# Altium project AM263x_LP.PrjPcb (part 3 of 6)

## Sheet PROC111_AM263x_7_PRU.SchDoc
size 431 x 279 mm; Date: Not shown in title block; ApprovedBy: Not shown in title block; CheckedBy: Not shown in title block; Author: Not shown in title block; CompanyName: Not shown in title block; Engineer: Not shown in title block; Organization: Not shown in title block; Address1: Not shown in title block; Address2: Not shown in title block; Address3: Not shown in title block; Address4: Not shown in title block; DocumentNumber: 11; Revision: Use project parameter SCH_Rev; SheetNumber: 11; SheetTotal: 24; PageSetup: Record=PageOptions¦CenterHorizontal=True¦CenterVertical=True¦PrintScale=1.00¦XCorrection=1.00¦YCorrection=1.00¦PrintKind=0¦BorderSize=5000000¦LeftOffset=0¦BottomOffset=0¦Orientation=2¦PaperLength=1000¦PaperWidth=1000¦Scale=100¦PaperSource=15¦PrintQuality=600¦MediaType=1¦DitherType=10¦PaperKind=Letter¦PrintScaleMode=1
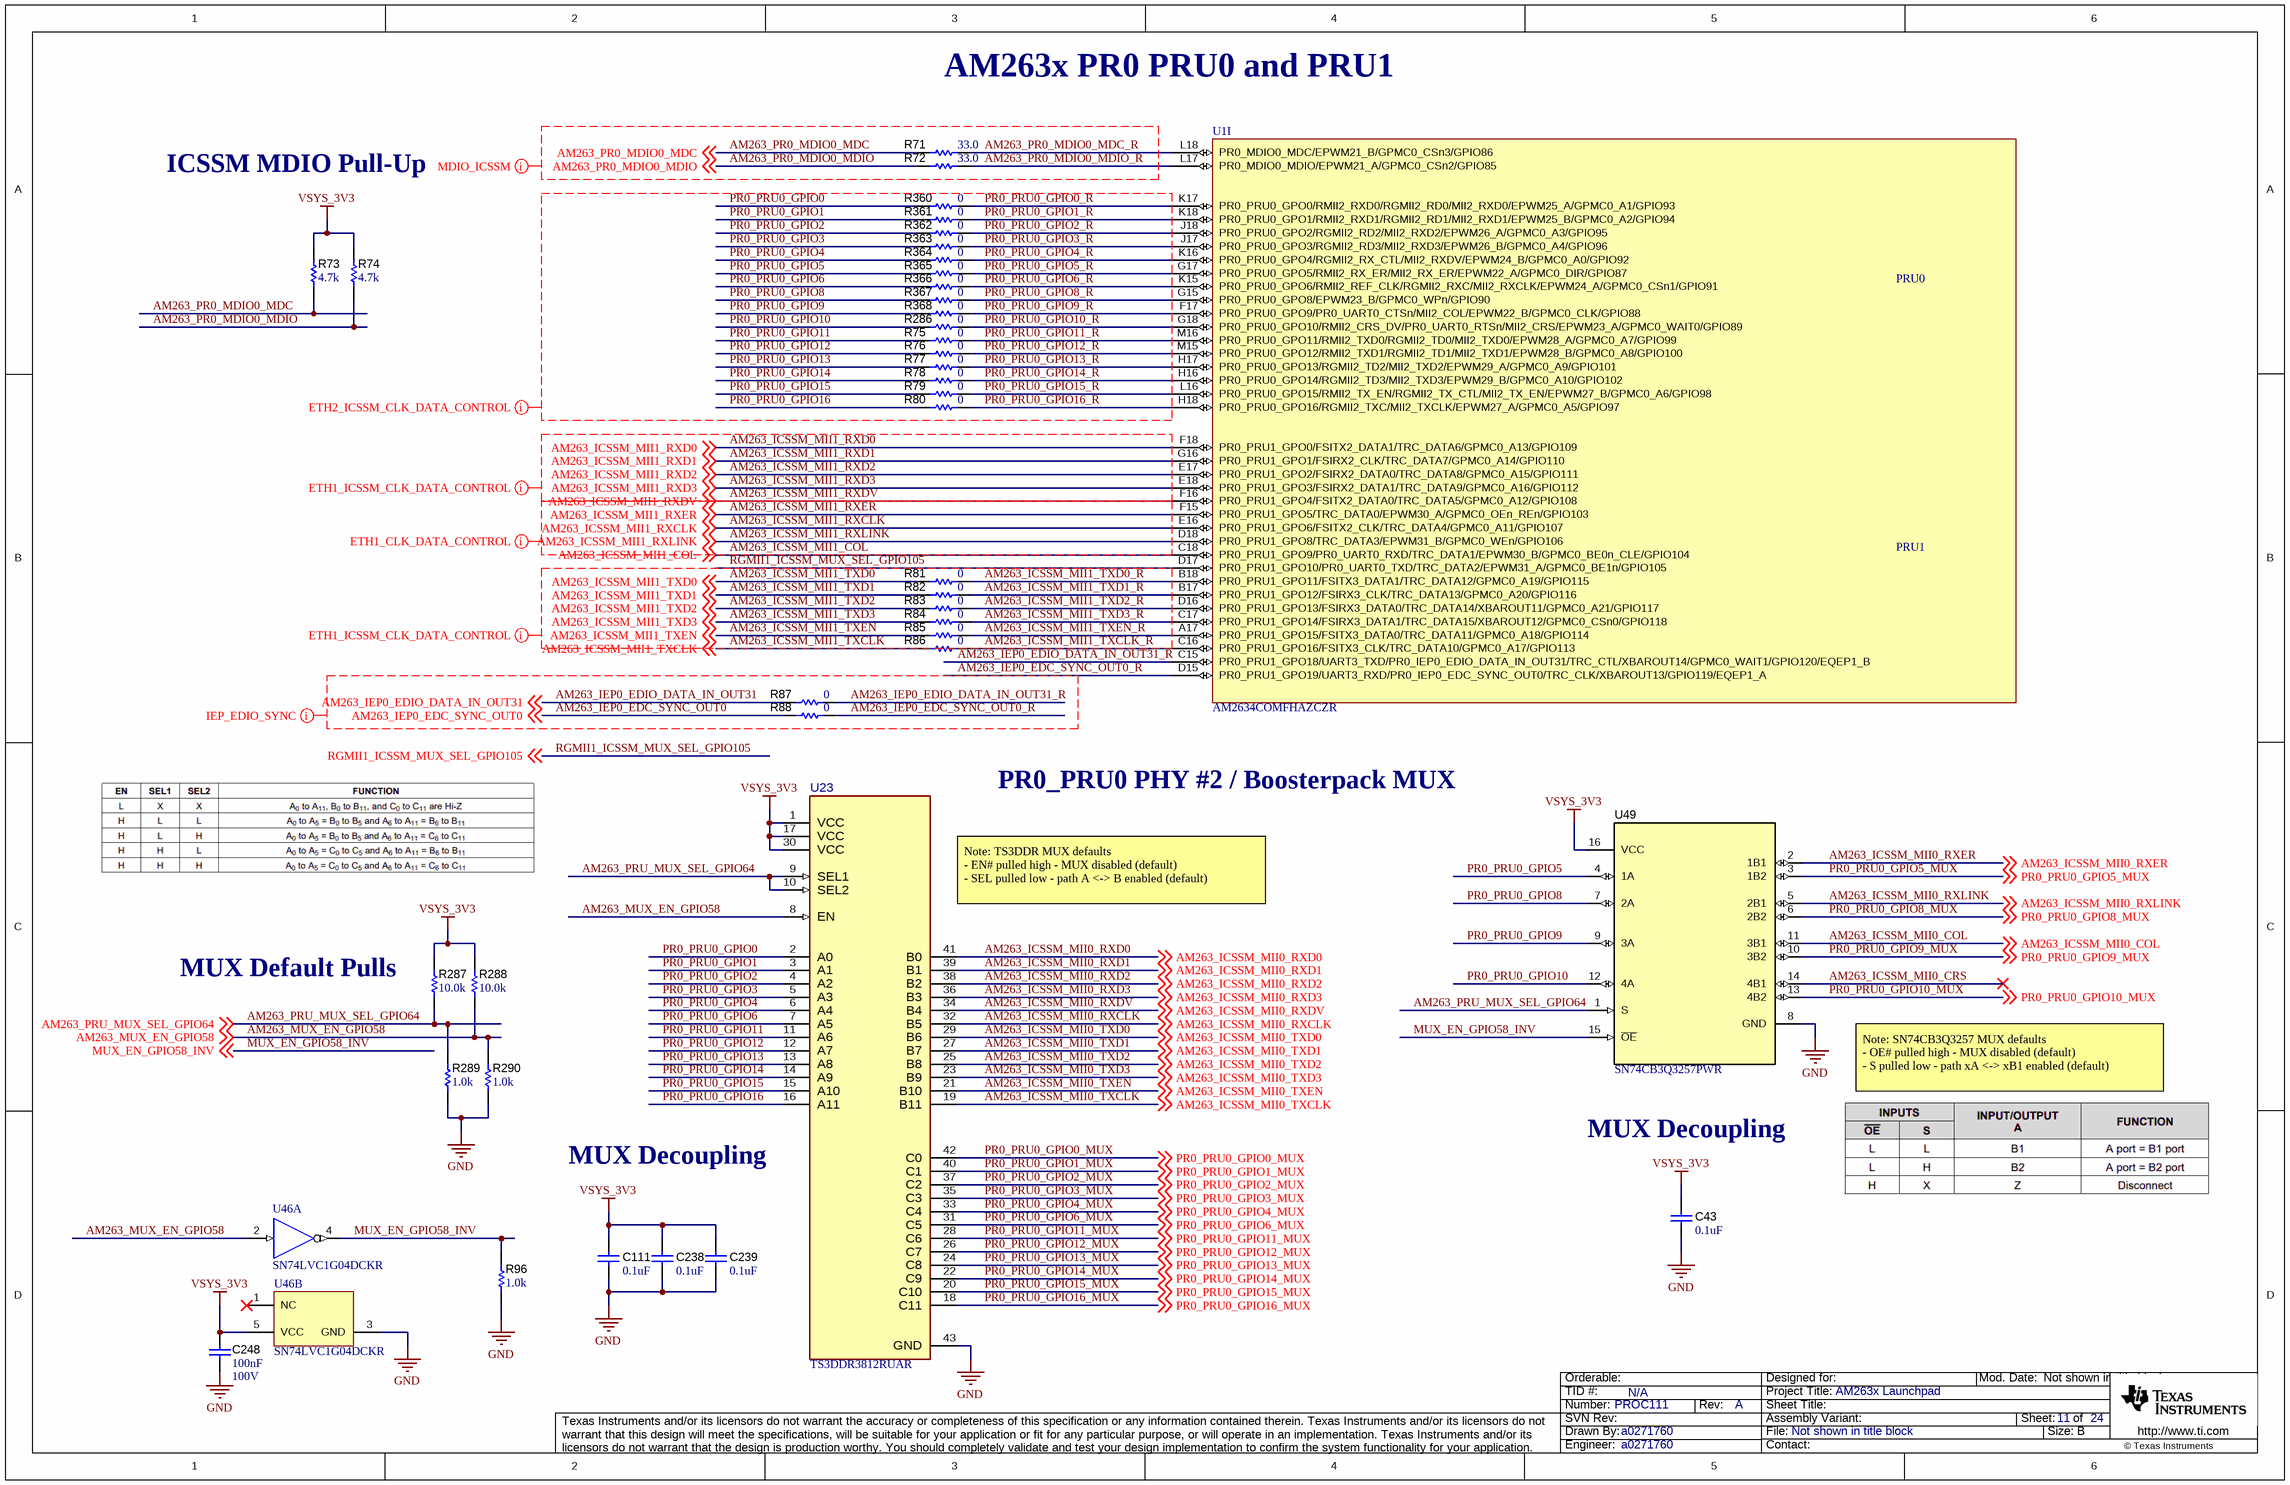
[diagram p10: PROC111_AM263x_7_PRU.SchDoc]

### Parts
C43  ValueDisplayed: 0.1uF  [0402]  (hidden comment: GRM155R71E104KE14D)
C111  ValueDisplayed: 0.1uF  [0402]  (hidden comment: GRM155R71E104KE14D)
C238  ValueDisplayed: 0.1uF  [0402]  (hidden comment: GRM155R71E104KE14D)
C239  ValueDisplayed: 0.1uF  [0402]  (hidden comment: GRM155R71E104KE14D)
C248  Cap_F: 100nF  VDC_V: 100V  [0603]  (hidden comment: GRM188R72A104KA35D)
R71  ValueDisplayed: 33.0  [0402L]  (hidden comment: ERJ-2RKF33R0X)
R72  ValueDisplayed: 33.0  [0402L]  (hidden comment: ERJ-2RKF33R0X)
R73  ValueDisplayed: 4.7k  [0402]  (hidden comment: CRCW04024K70JNED)
R74  ValueDisplayed: 4.7k  [0402]  (hidden comment: CRCW04024K70JNED)
R75  value 0  [0402L]  (hidden comment: ERJ-2GE0R00X)
R76  value 0  [0402L]  (hidden comment: ERJ-2GE0R00X)
R77  value 0  [0402L]  (hidden comment: ERJ-2GE0R00X)
R78  value 0  [0402L]  (hidden comment: ERJ-2GE0R00X)
R79  value 0  [0402L]  (hidden comment: ERJ-2GE0R00X)
R80  value 0  [0402L]  (hidden comment: ERJ-2GE0R00X)
R81  value 0  [0402L]  (hidden comment: ERJ-2GE0R00X)
R82  value 0  [0402L]  (hidden comment: ERJ-2GE0R00X)
R83  value 0  [0402L]  (hidden comment: ERJ-2GE0R00X)
R84  value 0  [0402L]  (hidden comment: ERJ-2GE0R00X)
R85  value 0  [0402L]  (hidden comment: ERJ-2GE0R00X)
R86  value 0  [0402L]  (hidden comment: ERJ-2GE0R00X)
R87  value 0  [0402L]  (hidden comment: ERJ-2GE0R00X)
R88  value 0  [0402L]  (hidden comment: ERJ-2GE0R00X)
R96  ValueDisplayed: 1.0k  [0402]  (hidden comment: ERJ-2GEJ102X)
R286  value 0  [0402L]  (hidden comment: ERJ-2GE0R00X)
R287  ValueDisplayed: 10.0k  [0402]  (hidden comment: ERJ-2RKF1002X)
R288  ValueDisplayed: 10.0k  [0402]  (hidden comment: ERJ-2RKF1002X)
R289  ValueDisplayed: 1.0k  [0402]  (hidden comment: ERJ-2GEJ102X)
R290  ValueDisplayed: 1.0k  [0402]  (hidden comment: ERJ-2GEJ102X)
R360  value 0  [0402L]  (hidden comment: ERJ-2GE0R00X)
R361  value 0  [0402L]  (hidden comment: ERJ-2GE0R00X)
R362  value 0  [0402L]  (hidden comment: ERJ-2GE0R00X)
R363  value 0  [0402L]  (hidden comment: ERJ-2GE0R00X)
R364  value 0  [0402L]  (hidden comment: ERJ-2GE0R00X)
R365  value 0  [0402L]  (hidden comment: ERJ-2GE0R00X)
R366  value 0  [0402L]  (hidden comment: ERJ-2GE0R00X)
R367  value 0  [0402L]  (hidden comment: ERJ-2GE0R00X)
R368  value 0  [0402L]  (hidden comment: ERJ-2GE0R00X)
U1  AM2634COMFHAZCZR  [ZCZ (S-PBGA-N324)]  (part I of 13)
U23  TS3DDR3812RUAR  [RUA0042A-MFG]
U46  SN74LVC1G04DCKR  [DCK0005A_N]  (parts A,B of 2)
U49  SN74CB3Q3257PWR  [PW0016A_L]

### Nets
GND: C43.1 C111.1 C238.1 C239.1 C248.2 R96.1 R289.1 R290.1 U23.43(GND) U46.3(GND) U49.8(GND)
VSYS_3V3: C43.2 C111.2 C238.2 C239.2 C248.1 R73.2 R74.2 R287.1 R288.1 U23.1(VCC) U23.17(VCC) U23.30(VCC) U46.5(VCC) U49.16(VCC)
AM263_ICSSM_MII0_COL: U49.11(3B1) ; off-sheet AM263_ICSSM_MII0_COL
AM263_ICSSM_MII0_CRS: U49.14(4B1)
AM263_ICSSM_MII0_RXCLK: U23.32(B5) ; off-sheet AM263_ICSSM_MII0_RXCLK
AM263_ICSSM_MII0_RXD0: U23.41(B0) ; off-sheet AM263_ICSSM_MII0_RXD0
AM263_ICSSM_MII0_RXD1: U23.39(B1) ; off-sheet AM263_ICSSM_MII0_RXD1
AM263_ICSSM_MII0_RXD2: U23.38(B2) ; off-sheet AM263_ICSSM_MII0_RXD2
AM263_ICSSM_MII0_RXD3: U23.36(B3) ; off-sheet AM263_ICSSM_MII0_RXD3
AM263_ICSSM_MII0_RXDV: U23.34(B4) ; off-sheet AM263_ICSSM_MII0_RXDV
AM263_ICSSM_MII0_RXER: U49.2(1B1) ; off-sheet AM263_ICSSM_MII0_RXER
AM263_ICSSM_MII0_RXLINK: U49.5(2B1) ; off-sheet AM263_ICSSM_MII0_RXLINK
AM263_ICSSM_MII0_TXCLK: U23.19(B11) ; off-sheet AM263_ICSSM_MII0_TXCLK
AM263_ICSSM_MII0_TXD0: U23.29(B6) ; off-sheet AM263_ICSSM_MII0_TXD0
AM263_ICSSM_MII0_TXD1: U23.27(B7) ; off-sheet AM263_ICSSM_MII0_TXD1
AM263_ICSSM_MII0_TXD2: U23.25(B8) ; off-sheet AM263_ICSSM_MII0_TXD2
AM263_ICSSM_MII0_TXD3: U23.23(B9) ; off-sheet AM263_ICSSM_MII0_TXD3
AM263_ICSSM_MII0_TXEN: U23.21(B10) ; off-sheet AM263_ICSSM_MII0_TXEN
AM263_ICSSM_MII1_COL: U1.C18(PR0_PRU1_GPO9/PR0_UART0_RXD/TRC_DATA1/EPWM30_B/GPMC0_BE0n_CLE/GPIO104) ; off-sheet AM263_ICSSM_MII1_COL
AM263_ICSSM_MII1_RXCLK: U1.E16(PR0_PRU1_GPO6/FSITX2_CLK/TRC_DATA4/GPMC0_A11/GPIO107) ; off-sheet AM263_ICSSM_MII1_RXCLK
AM263_ICSSM_MII1_RXD0: U1.F18(PR0_PRU1_GPO0/FSITX2_DATA1/TRC_DATA6/GPMC0_A13/GPIO109) ; off-sheet AM263_ICSSM_MII1_RXD0
AM263_ICSSM_MII1_RXD1: U1.G16(PR0_PRU1_GPO1/FSIRX2_CLK/TRC_DATA7/GPMC0_A14/GPIO110) ; off-sheet AM263_ICSSM_MII1_RXD1
AM263_ICSSM_MII1_RXD2: U1.E17(PR0_PRU1_GPO2/FSIRX2_DATA0/TRC_DATA8/GPMC0_A15/GPIO111) ; off-sheet AM263_ICSSM_MII1_RXD2
AM263_ICSSM_MII1_RXD3: U1.E18(PR0_PRU1_GPO3/FSIRX2_DATA1/TRC_DATA9/GPMC0_A16/GPIO112) ; off-sheet AM263_ICSSM_MII1_RXD3
AM263_ICSSM_MII1_RXDV: U1.F16(PR0_PRU1_GPO4/FSITX2_DATA0/TRC_DATA5/GPMC0_A12/GPIO108) ; off-sheet AM263_ICSSM_MII1_RXDV
AM263_ICSSM_MII1_RXER: U1.F15(PR0_PRU1_GPO5/TRC_DATA0/EPWM30_A/GPMC0_OEn_REn/GPIO103) ; off-sheet AM263_ICSSM_MII1_RXER
AM263_ICSSM_MII1_RXLINK: U1.D18(PR0_PRU1_GPO8/TRC_DATA3/EPWM31_B/GPMC0_WEn/GPIO106) ; off-sheet AM263_ICSSM_MII1_RXLINK
AM263_ICSSM_MII1_TXCLK: R86.1 ; off-sheet AM263_ICSSM_MII1_TXCLK
AM263_ICSSM_MII1_TXCLK_R: R86.2 U1.C16(PR0_PRU1_GPO16/FSITX3_CLK/TRC_DATA10/GPMC0_A17/GPIO113)
AM263_ICSSM_MII1_TXD0: R81.1 ; off-sheet AM263_ICSSM_MII1_TXD0
AM263_ICSSM_MII1_TXD0_R: R81.2 U1.B18(PR0_PRU1_GPO11/FSITX3_DATA1/TRC_DATA12/GPMC0_A19/GPIO115)
AM263_ICSSM_MII1_TXD1: R82.1 ; off-sheet AM263_ICSSM_MII1_TXD1
AM263_ICSSM_MII1_TXD1_R: R82.2 U1.B17(PR0_PRU1_GPO12/FSIRX3_CLK/TRC_DATA13/GPMC0_A20/GPIO116)
AM263_ICSSM_MII1_TXD2: R83.1 ; off-sheet AM263_ICSSM_MII1_TXD2
AM263_ICSSM_MII1_TXD2_R: R83.2 U1.D16(PR0_PRU1_GPO13/FSIRX3_DATA0/TRC_DATA14/XBAROUT11/GPMC0_A21/GPIO117)
AM263_ICSSM_MII1_TXD3: R84.1 ; off-sheet AM263_ICSSM_MII1_TXD3
AM263_ICSSM_MII1_TXD3_R: R84.2 U1.C17(PR0_PRU1_GPO14/FSIRX3_DATA1/TRC_DATA15/XBAROUT12/GPMC0_CSn0/GPIO118)
AM263_ICSSM_MII1_TXEN: R85.1 ; off-sheet AM263_ICSSM_MII1_TXEN
AM263_ICSSM_MII1_TXEN_R: R85.2 U1.A17(PR0_PRU1_GPO15/FSITX3_DATA0/TRC_DATA11/GPMC0_A18/GPIO114)
AM263_IEP0_EDC_SYNC_OUT0: R88.1 ; off-sheet AM263_IEP0_EDC_SYNC_OUT0
AM263_IEP0_EDC_SYNC_OUT0_R: R88.2 U1.D15(PR0_PRU1_GPO19/UART3_RXD/PR0_IEP0_EDC_SYNC_OUT0/TRC_CLK/XBAROUT13/GPIO119/EQEP1_A)
AM263_IEP0_EDIO_DATA_IN_OUT31: R87.1 ; off-sheet AM263_IEP0_EDIO_DATA_IN_OUT31
AM263_IEP0_EDIO_DATA_IN_OUT31_R: R87.2 U1.C15(PR0_PRU1_GPO18/UART3_TXD/PR0_IEP0_EDIO_DATA_IN_OUT31/TRC_CTL/XBAROUT14/GPMC0_WAIT1/GPIO120/EQEP1_B)
AM263_MUX_EN_GPIO58: R288.2 R290.2 U23.8(EN) U46.2(A) ; off-sheet AM263_MUX_EN_GPIO58
AM263_PR0_MDIO0_MDC: R71.1 R73.1 ; off-sheet AM263_PR0_MDIO0_MDC
AM263_PR0_MDIO0_MDC_R: R71.2 U1.L18(PR0_MDIO0_MDC/EPWM21_B/GPMC0_CSn3/GPIO86)
AM263_PR0_MDIO0_MDIO: R72.1 R74.1 ; off-sheet AM263_PR0_MDIO0_MDIO
AM263_PR0_MDIO0_MDIO_R: R72.2 U1.L17(PR0_MDIO0_MDIO/EPWM21_A/GPMC0_CSn2/GPIO85)
AM263_PRU_MUX_SEL_GPIO64: R287.2 R289.2 U23.9(SEL1) U23.10(SEL2) U49.1(S) ; off-sheet AM263_PRU_MUX_SEL_GPIO64
MUX_EN_GPIO58_INV: R96.2 U46.4(Y) U49.15(~{OE}) ; off-sheet MUX_EN_GPIO58_INV
PR0_PRU0_GPIO0: R360.1 U23.2(A0)
PR0_PRU0_GPIO0_MUX: U23.42(C0) ; off-sheet PR0_PRU0_GPIO0_MUX
PR0_PRU0_GPIO0_R: R360.2 U1.K17(PR0_PRU0_GPO0/RMII2_RXD0/RGMII2_RD0/MII2_RXD0/EPWM25_A/GPMC0_A1/GPIO93)
PR0_PRU0_GPIO1: R361.1 U23.3(A1)
PR0_PRU0_GPIO1_MUX: U23.40(C1) ; off-sheet PR0_PRU0_GPIO1_MUX
PR0_PRU0_GPIO1_R: R361.2 U1.K18(PR0_PRU0_GPO1/RMII2_RXD1/RGMII2_RD1/MII2_RXD1/EPWM25_B/GPMC0_A2/GPIO94)
PR0_PRU0_GPIO2: R362.1 U23.4(A2)
PR0_PRU0_GPIO2_MUX: U23.37(C2) ; off-sheet PR0_PRU0_GPIO2_MUX
PR0_PRU0_GPIO2_R: R362.2 U1.J18(PR0_PRU0_GPO2/RGMII2_RD2/MII2_RXD2/EPWM26_A/GPMC0_A3/GPIO95)
PR0_PRU0_GPIO3: R363.1 U23.5(A3)
PR0_PRU0_GPIO3_MUX: U23.35(C3) ; off-sheet PR0_PRU0_GPIO3_MUX
PR0_PRU0_GPIO3_R: R363.2 U1.J17(PR0_PRU0_GPO3/RGMII2_RD3/MII2_RXD3/EPWM26_B/GPMC0_A4/GPIO96)
PR0_PRU0_GPIO4: R364.1 U23.6(A4)
PR0_PRU0_GPIO4_MUX: U23.33(C4) ; off-sheet PR0_PRU0_GPIO4_MUX
PR0_PRU0_GPIO4_R: R364.2 U1.K16(PR0_PRU0_GPO4/RGMII2_RX_CTL/MII2_RXDV/EPWM24_B/GPMC0_A0/GPIO92)
PR0_PRU0_GPIO5: R365.1 U49.4(1A)
PR0_PRU0_GPIO5_MUX: U49.3(1B2) ; off-sheet PR0_PRU0_GPIO5_MUX
PR0_PRU0_GPIO5_R: R365.2 U1.G17(PR0_PRU0_GPO5/RMII2_RX_ER/MII2_RX_ER/EPWM22_A/GPMC0_DIR/GPIO87)
PR0_PRU0_GPIO6: R366.1 U23.7(A5)
PR0_PRU0_GPIO6_MUX: U23.31(C5) ; off-sheet PR0_PRU0_GPIO6_MUX
PR0_PRU0_GPIO6_R: R366.2 U1.K15(PR0_PRU0_GPO6/RMII2_REF_CLK/RGMII2_RXC/MII2_RXCLK/EPWM24_A/GPMC0_CSn1/GPIO91)
PR0_PRU0_GPIO8: R367.1 U49.7(2A)
PR0_PRU0_GPIO8_MUX: U49.6(2B2) ; off-sheet PR0_PRU0_GPIO8_MUX
PR0_PRU0_GPIO8_R: R367.2 U1.G15(PR0_PRU0_GPO8/EPWM23_B/GPMC0_WPn/GPIO90)
PR0_PRU0_GPIO9: R368.1 U49.9(3A)
PR0_PRU0_GPIO9_MUX: U49.10(3B2) ; off-sheet PR0_PRU0_GPIO9_MUX
PR0_PRU0_GPIO9_R: R368.2 U1.F17(PR0_PRU0_GPO9/PR0_UART0_CTSn/MII2_COL/EPWM22_B/GPMC0_CLK/GPIO88)
PR0_PRU0_GPIO10: R286.1 U49.12(4A)
PR0_PRU0_GPIO10_MUX: U49.13(4B2) ; off-sheet PR0_PRU0_GPIO10_MUX
PR0_PRU0_GPIO10_R: R286.2 U1.G18(PR0_PRU0_GPO10/RMII2_CRS_DV/PR0_UART0_RTSn/MII2_CRS/EPWM23_A/GPMC0_WAIT0/GPIO89)
PR0_PRU0_GPIO11: R75.1 U23.11(A6)
PR0_PRU0_GPIO11_MUX: U23.28(C6) ; off-sheet PR0_PRU0_GPIO11_MUX
PR0_PRU0_GPIO11_R: R75.2 U1.M16(PR0_PRU0_GPO11/RMII2_TXD0/RGMII2_TD0/MII2_TXD0/EPWM28_A/GPMC0_A7/GPIO99)
PR0_PRU0_GPIO12: R76.1 U23.12(A7)
PR0_PRU0_GPIO12_MUX: U23.26(C7) ; off-sheet PR0_PRU0_GPIO12_MUX
PR0_PRU0_GPIO12_R: R76.2 U1.M15(PR0_PRU0_GPO12/RMII2_TXD1/RGMII2_TD1/MII2_TXD1/EPWM28_B/GPMC0_A8/GPIO100)
PR0_PRU0_GPIO13: R77.1 U23.13(A8)
PR0_PRU0_GPIO13_MUX: U23.24(C8) ; off-sheet PR0_PRU0_GPIO13_MUX
PR0_PRU0_GPIO13_R: R77.2 U1.H17(PR0_PRU0_GPO13/RGMII2_TD2/MII2_TXD2/EPWM29_A/GPMC0_A9/GPIO101)
PR0_PRU0_GPIO14: R78.1 U23.14(A9)
PR0_PRU0_GPIO14_MUX: U23.22(C9) ; off-sheet PR0_PRU0_GPIO14_MUX
PR0_PRU0_GPIO14_R: R78.2 U1.H16(PR0_PRU0_GPO14/RGMII2_TD3/MII2_TXD3/EPWM29_B/GPMC0_A10/GPIO102)
PR0_PRU0_GPIO15: R79.1 U23.15(A10)
PR0_PRU0_GPIO15_MUX: U23.20(C10) ; off-sheet PR0_PRU0_GPIO15_MUX
PR0_PRU0_GPIO15_R: R79.2 U1.L16(PR0_PRU0_GPO15/RMII2_TX_EN/RGMII2_TX_CTL/MII2_TX_EN/EPWM27_B/GPMC0_A6/GPIO98)
PR0_PRU0_GPIO16: R80.1 U23.16(A11)
PR0_PRU0_GPIO16_MUX: U23.18(C11) ; off-sheet PR0_PRU0_GPIO16_MUX
PR0_PRU0_GPIO16_R: R80.2 U1.H18(PR0_PRU0_GPO16/RGMII2_TXC/MII2_TXCLK/EPWM27_A/GPMC0_A5/GPIO97)
RGMII1_ICSSM_MUX_SEL_GPIO105: U1.D17(PR0_PRU1_GPO10/PR0_UART0_TXD/TRC_DATA2/EPWM31_A/GPMC0_BE1n/GPIO105) ; off-sheet RGMII1_ICSSM_MUX_SEL_GPIO105

Not connected (* = marked no-connect by the designer): U46 1(NC)*

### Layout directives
mark named IEP_EDIO_SYNC: AM263_IEP0_EDC_SYNC_OUT0, AM263_IEP0_EDC_SYNC_OUT0_R, AM263_IEP0_EDIO_DATA_IN_OUT31, AM263_IEP0_EDIO_DATA_IN_OUT31_R
mark named ETH2_ICSSM_CLK_DATA_CONTROL: PR0_PRU0_GPIO0, PR0_PRU0_GPIO0_R, PR0_PRU0_GPIO1, PR0_PRU0_GPIO1_R, PR0_PRU0_GPIO2, PR0_PRU0_GPIO2_R, PR0_PRU0_GPIO3, PR0_PRU0_GPIO3_R, PR0_PRU0_GPIO4, PR0_PRU0_GPIO4_R, PR0_PRU0_GPIO5, PR0_PRU0_GPIO5_R, PR0_PRU0_GPIO6, PR0_PRU0_GPIO6_R, PR0_PRU0_GPIO8, PR0_PRU0_GPIO8_R, PR0_PRU0_GPIO9, PR0_PRU0_GPIO9_R, PR0_PRU0_GPIO10, PR0_PRU0_GPIO10_R, PR0_PRU0_GPIO11, PR0_PRU0_GPIO11_R, PR0_PRU0_GPIO12, PR0_PRU0_GPIO12_R, PR0_PRU0_GPIO13, PR0_PRU0_GPIO13_R, PR0_PRU0_GPIO14, PR0_PRU0_GPIO14_R, PR0_PRU0_GPIO15, PR0_PRU0_GPIO15_R, PR0_PRU0_GPIO16, PR0_PRU0_GPIO16_R
mark named ETH1_ICSSM_CLK_DATA_CONTROL: AM263_ICSSM_MII1_RXD0, AM263_ICSSM_MII1_RXD1, AM263_ICSSM_MII1_RXD2, AM263_ICSSM_MII1_RXD3, AM263_ICSSM_MII1_RXDV, AM263_ICSSM_MII1_TXCLK, AM263_ICSSM_MII1_TXCLK_R, AM263_ICSSM_MII1_TXD0, AM263_ICSSM_MII1_TXD0_R, AM263_ICSSM_MII1_TXD1, AM263_ICSSM_MII1_TXD1_R, AM263_ICSSM_MII1_TXD2, AM263_ICSSM_MII1_TXD2_R, AM263_ICSSM_MII1_TXD3, AM263_ICSSM_MII1_TXD3_R, AM263_ICSSM_MII1_TXEN, AM263_ICSSM_MII1_TXEN_R, RGMII1_ICSSM_MUX_SEL_GPIO105
mark named MDIO_ICSSM: AM263_PR0_MDIO0_MDC, AM263_PR0_MDIO0_MDC_R, AM263_PR0_MDIO0_MDIO, AM263_PR0_MDIO0_MDIO_R
mark named ETH1_CLK_DATA_CONTROL: AM263_ICSSM_MII1_COL, AM263_ICSSM_MII1_RXCLK, AM263_ICSSM_MII1_RXDV, AM263_ICSSM_MII1_RXER, AM263_ICSSM_MII1_RXLINK

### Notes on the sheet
- AM263x PR0 PRU0 and PRU1
- ICSSM MDIO Pull-Up
- PR0_PRU0 PHY #2 / Boosterpack MUX
- (near U23) Note: TS3DDR MUX defaults
  - EN# pulled high - MUX disabled (default)
  - SEL pulled low - path A <-> B enabled (default)
- (near R287) MUX Default Pulls
- Note: SN74CB3Q3257 MUX defaults
  - OE# pulled high - MUX disabled (default)
  - S pulled low - path xA <-> xB1 enabled (default)
- MUX Decoupling

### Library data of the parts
C43 C111 C238 C239 = CMP-0006659-2: CAP, CERM, 0.1 uF, 25 V, +/- 10%, X7R, 0402; Manufacturer: MuRata; TaMin_C: -55°C; Polarized: N; SizeAreaWB_mm2: 3; U/M: EA; Value: 0.1uF; TaMax_C: 125°C; SizeZ_mm: 0.6; SizeX_mm: 1; SizeY_mm: 0.5; Value2: 25V; Cap_F: 100nF; AEC Category: Q200; Value1: Unknown
C248 = CMP-0007469-4: CAP, CERM, 0.1 uF, 100 V, +/- 10%, X7R, 0603; Manufacturer: MuRata; TaMin_C: -55°C; Polarized: N; SizeAreaWB_mm2: 4.68; Value1: Unknown; U/M: EA; Value: 0.1uF; TaMax_C: 125°C; SizeZ_mm: 1; SizeX_mm: 1.6; SizeY_mm: 0.8; SizeArea_mm2: 1.28; AEC Category: Q200
R71 R72 = CMP-0026696-1: RES, 33.0, 1%, 0.1 W, 0402; Manufacturer: Panasonic; Power_W: 100mW; TempCo: 100 ppm/C; Value_Code: 33R0; U/M: EA; Value: 33.0; Res_ohm: 33; SizeX_mm: 1; SizeY_mm: 0.5; SizeZ_mm: 0.6; Value2: 0.1W; VDC_V: 50V; AEC Category: Q200
R73 R74 = CMP-0026938-5: RES, 4.7 k, 5%, 0.063 W, AEC-Q200 Grade 0, 0402; Manufacturer: Vishay-Dale; Power_W: 63mW; TempCo: 200 ppm/C; Value_Code: 4k70; Value: 4.7k; EIA_Code: E24; SizeX_mm: 1; SizeY_mm: 0.5; SizeZ_mm: 0.6; Value2: 0.063W; AEC Qualified: Y; VDC_V: 50V; AEC Category: Q200; AEC Grade: 0
R75-R88 R286 R360-R368 = CMP-0026992-3: RES, 0, 5%, 0.1 W, AEC-Q200 Grade 0, 0402; Manufacturer: Panasonic; Power_W: 100mW; TempCo: 600 ppm/C; Value_Code: 0000; EIA_Code: E24; SizeX_mm: 1; SizeY_mm: 0.5; SizeZ_mm: 0.6; Value2: 0.1W; AEC Qualified: Y; VDC_V: 50V; AEC Category: Q200; SizeAreaWB_mm2: 3
R96 R289 R290 = CMP-0078193-1: RES, 1.0 k, 5%, 0.1 W, AEC-Q200 Grade 0, 0402; Manufacturer: Panasonic; Value_Code: 1k00; SizeArea_mm2: 0.5; AEC Qualified: Y; AEC Category: Q200; Res_ohm: 1k; Value: 1.0k; SizeZ_mm: 0.6; Green_REACh: Passed; EIA_Code: E24; TempCo: 200 ppm/C; AEC Grade: 0; Power_W: 100mW; VDC_V: 50V; Value2: 0.1W; Green_Lifecycle: Active; U/M: EA; SizeX_mm: 1
R287 R288 = CMP-0026658-1: RES, 10.0 k, 1%, 0.1 W, 0402; Manufacturer: Panasonic; Power_W: 100mW; TempCo: 100 ppm/C; Value_Code: 10k0; U/M: EA; Value: 10.0k; EIA_Code: E96; Res_ohm: 10k; SizeX_mm: 1; SizeY_mm: 0.5; SizeZ_mm: 0.6; Value2: 0.1W; VDC_V: 50V; AEC Category: Q200
U1 = AM263x: Sitara AM263x MCU; Manufacturer: Texas Instruments
U23 = CMP-0093539-2: IC MUX/DEMUX DDR3 1:2 42WQFN; Manufacturer: Texas Instruments; TaMax_C: +85°C; TaMin_C: -40°C; On State Resistance: 8Ω; SizeZ_mm: 0.8mm; Min Supply Voltage: 3V; Standoff Height: 0mm; Max Supply Voltage: 3.6V; AEC Qualified: No; PositionCount: 12; -3Db Bandwith: 1.675GHz; Nominal Supply Current: 300uA; AEC Category: Q200
U46 = CMP-0051684-3: Single Inverter, DCK0005A, LARGE T&R; Manufacturer: Texas Instruments; Input Type: CMOS/TTL; Output Drive (IOL/IOH)(Max)(mA): 32/-32; Sub-Family: Inverting Buffer/Driver; VCC(Min)(V): 1.65; Bits(#): 1; Schmitt Trigger: No; Technology Family: LVC; Rating: Catalog; ICC @ Nom Voltage(Max)(mA): 0.01; tpd @ Nom Voltage(Max)(ns): 7.5,5.2,4.2,3.7; Voltage(Nom)(V): 1.8,2.5,3.3,5; F @ Nom Voltage(Max)(Mhz): 150; Output Type: CMOS; VCC(Max)(V): 5.5; Logic: Inverting; AEC Category: Q200; AEC Qualified: N; CompType: IC; SizeAreaWB_mm2: 9.3; SizeArea_mm2: 4.2; SizeX_mm: 2.1; SizeY_mm: 2.0; SizeZ_mm: 1.1
U49 = CMP-0076540-1: 4-Bit One-of-2 FET Multiplexer/Demultiplexer 2.5-V/3.3-V Low-Voltage, High-Bandwidth Bus Switch, PW0016A (TSSOP-16); Manufacturer: Texas Instruments; SizeAreaWB_mm2: 58.8; SizeArea_mm2: 32.0; SizeZ_mm: 1.2; SizeY_mm: 5.0; U/M: EA; CompType: IC; SizeX_mm: 6.4

## Sheet PROC111_AM263x_8_SDFM.SchDoc
size 431 x 279 mm; Date: Not shown in title block; ApprovedBy: Not shown in title block; CheckedBy: Not shown in title block; Author: Not shown in title block; CompanyName: Not shown in title block; Engineer: Not shown in title block; Organization: Not shown in title block; Address1: Not shown in title block; Address2: Not shown in title block; Address3: Not shown in title block; Address4: Not shown in title block; DocumentNumber: 12; Revision: Use project parameter SCH_Rev; SheetNumber: 12; SheetTotal: 24; PageSetup: Record=PageOptions¦CenterHorizontal=True¦CenterVertical=True¦PrintScale=1.00¦XCorrection=1.00¦YCorrection=1.00¦PrintKind=0¦BorderSize=5000000¦LeftOffset=0¦BottomOffset=0¦Orientation=2¦PaperLength=1000¦PaperWidth=1000¦Scale=100¦PaperSource=15¦PrintQuality=600¦MediaType=1¦DitherType=10¦PaperKind=Letter¦PrintScaleMode=1
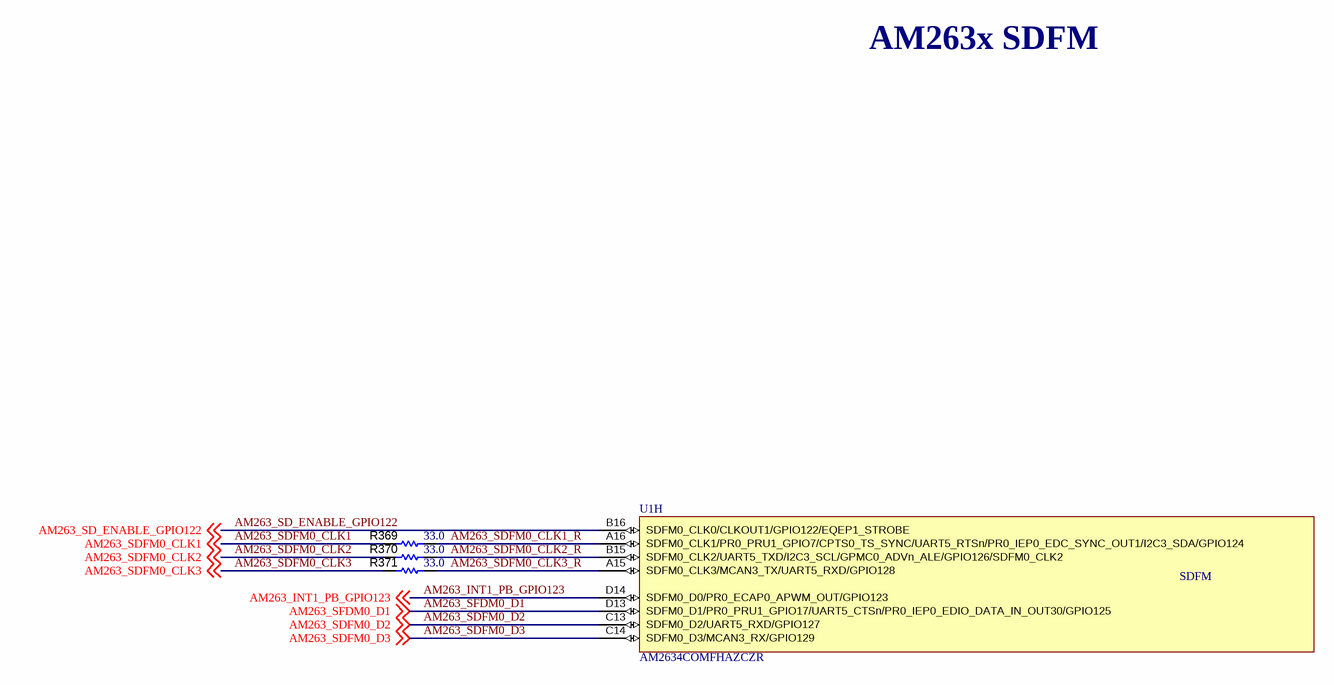
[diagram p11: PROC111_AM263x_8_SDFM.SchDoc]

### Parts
R369  ValueDisplayed: 33.0  [0402L]  (hidden comment: ERJ-2RKF33R0X)
R370  ValueDisplayed: 33.0  [0402L]  (hidden comment: ERJ-2RKF33R0X)
R371  ValueDisplayed: 33.0  [0402L]  (hidden comment: ERJ-2RKF33R0X)
U1  AM2634COMFHAZCZR  [ZCZ (S-PBGA-N324)]  (part H of 13)

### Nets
AM263_INT1_PB_GPIO123: U1.D14(SDFM0_D0/PR0_ECAP0_APWM_OUT/GPIO123) ; off-sheet AM263_INT1_PB_GPIO123
AM263_SD_ENABLE_GPIO122: U1.B16(SDFM0_CLK0/CLKOUT1/GPIO122/EQEP1_STROBE) ; off-sheet AM263_SD_ENABLE_GPIO122
AM263_SDFM0_CLK1: R369.1 ; off-sheet AM263_SDFM0_CLK1
AM263_SDFM0_CLK1_R: R369.2 U1.A16(SDFM0_CLK1/PR0_PRU1_GPIO7/CPTS0_TS_SYNC/UART5_RTSn/PR0_IEP0_EDC_SYNC_OUT1/I2C3_SDA/GPIO124)
AM263_SDFM0_CLK2: R370.1 ; off-sheet AM263_SDFM0_CLK2
AM263_SDFM0_CLK2_R: R370.2 U1.B15(SDFM0_CLK2/UART5_TXD/I2C3_SCL/GPMC0_ADVn_ALE/GPIO126/SDFM0_CLK2)
AM263_SDFM0_CLK3: R371.1 ; off-sheet AM263_SDFM0_CLK3
AM263_SDFM0_CLK3_R: R371.2 U1.A15(SDFM0_CLK3/MCAN3_TX/UART5_RXD/GPIO128)
AM263_SDFM0_D2: U1.C13(SDFM0_D2/UART5_RXD/GPIO127) ; off-sheet AM263_SDFM0_D2
AM263_SDFM0_D3: U1.C14(SDFM0_D3/MCAN3_RX/GPIO129) ; off-sheet AM263_SDFM0_D3
AM263_SFDM0_D1: U1.D13(SDFM0_D1/PR0_PRU1_GPIO17/UART5_CTSn/PR0_IEP0_EDIO_DATA_IN_OUT30/GPIO125) ; off-sheet AM263_SFDM0_D1

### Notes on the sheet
- AM263x SDFM

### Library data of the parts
R369-R371 = CMP-0026696-1: as R71 on sheet PROC111_AM263x_7_PRU
U1 = AM263x: as U1 on sheet PROC111_AM263x_7_PRU

## Sheet PROC111_Push_Buttons.SchDoc
size 431 x 279 mm; Date: Not shown in title block; ApprovedBy: Not shown in title block; CheckedBy: Not shown in title block; Author: Not shown in title block; CompanyName: Not shown in title block; Engineer: Not shown in title block; Organization: Not shown in title block; Address1: Not shown in title block; Address2: Not shown in title block; Address3: Not shown in title block; Address4: Not shown in title block; DocumentNumber: 13; Revision: Use project parameter SCH_Rev; SheetNumber: 13; SheetTotal: 24; PageSetup: Record=PageOptions¦CenterHorizontal=True¦CenterVertical=True¦PrintScale=1.00¦XCorrection=1.00¦YCorrection=1.00¦PrintKind=0¦BorderSize=5000000¦LeftOffset=0¦BottomOffset=0¦Orientation=2¦PaperLength=1000¦PaperWidth=1000¦Scale=100¦PaperSource=15¦PrintQuality=600¦MediaType=1¦DitherType=10¦PaperKind=Letter¦PrintScaleMode=1
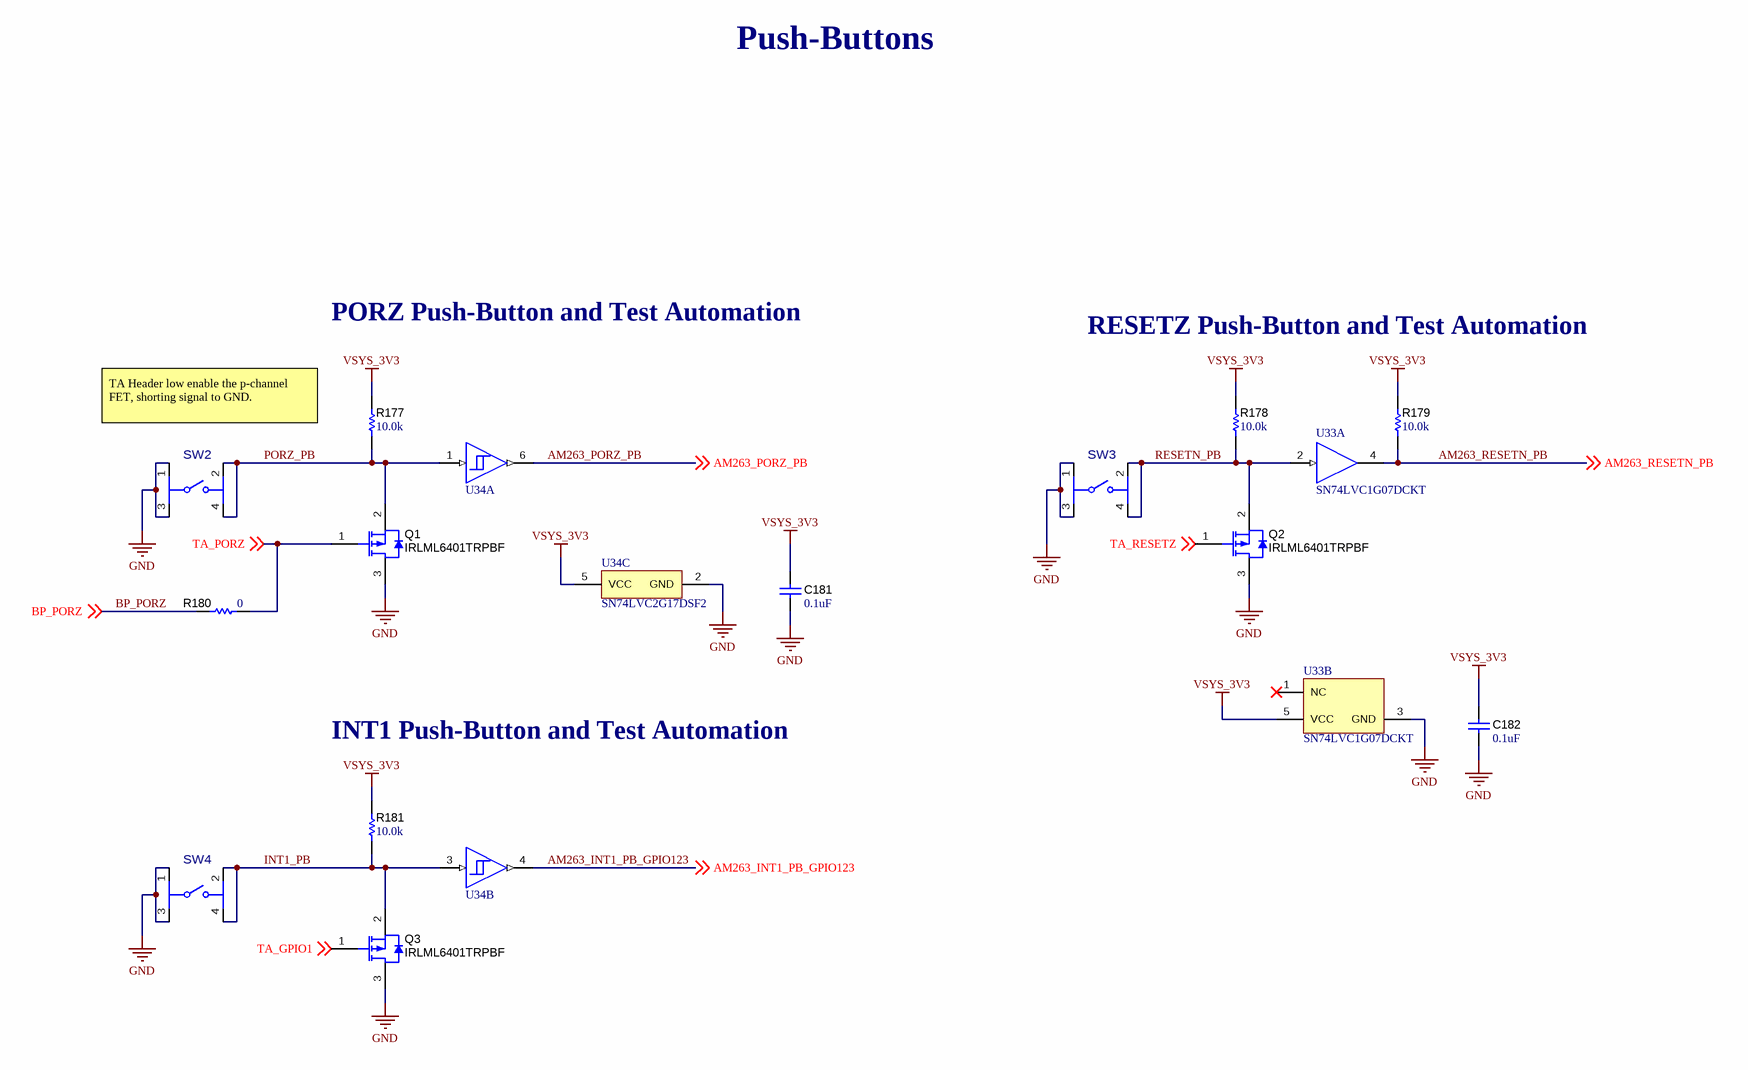
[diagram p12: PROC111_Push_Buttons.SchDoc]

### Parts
C181  ValueDisplayed: 0.1uF  [0402]  (hidden comment: GRM155R71E104KE14D)
C182  ValueDisplayed: 0.1uF  [0402]  (hidden comment: GRM155R71E104KE14D)
Q1  IRLML6401TRPBF  [SOT-23]
Q2  IRLML6401TRPBF  [SOT-23]
Q3  IRLML6401TRPBF  [SOT-23]
R177  ValueDisplayed: 10.0k  [0402]  (hidden comment: ERJ-2RKF1002X)
R178  ValueDisplayed: 10.0k  [0402]  (hidden comment: ERJ-2RKF1002X)
R179  ValueDisplayed: 10.0k  [0402]  (hidden comment: ERJ-2RKF1002X)
R180  ValueDisplayed: 0  [0402L]  (hidden comment: ERJ-2GE0R00X)
R181  ValueDisplayed: 10.0k  [0402]  (hidden comment: ERJ-2RKF1002X)
SW2  434351045816  [FP-434351045816_SMT_SW_4MM7_4MM5-MFG]  (value not drawn)
SW3  434351045816  [FP-434351045816_SMT_SW_4MM7_4MM5-MFG]  (value not drawn)
SW4  434351045816  [FP-434351045816_SMT_SW_4MM7_4MM5-MFG]  (value not drawn)
U33  SN74LVC1G07DCKT  [DCK0005A_N]  (parts A,B of 2)
U34  SN74LVC2G17DSF2  [DSF0006A]  (value not drawn)  (parts A,B,C of 3)

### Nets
GND: C181.1 C182.1 Q1.3(D) Q2.3(D) Q3.3(D) SW2.1 SW2.3 SW3.1 SW3.3 SW4.1 SW4.3 U33.3(GND) U34.2(GND)
VSYS_3V3: C181.2 C182.2 R177.2 R178.2 R179.2 R181.2 U33.5(VCC) U34.5(VCC)
AM263_INT1_PB_GPIO123: U34.4(2Y) ; off-sheet AM263_INT1_PB_GPIO123
AM263_PORZ_PB: U34.6(1Y) ; off-sheet AM263_PORZ_PB
AM263_RESETN_PB: R179.1 U33.4(Y) ; off-sheet AM263_RESETN_PB
BP_PORZ: R180.2 ; off-sheet BP_PORZ
INT1_PB: Q3.2(S) R181.1 SW4.2 SW4.4 U34.3(2A)
PORZ_PB: Q1.2(S) R177.1 SW2.2 SW2.4 U34.1(1A)
RESETN_PB: Q2.2(S) R178.1 SW3.2 SW3.4 U33.2(A)
TA_GPIO1: Q3.1(G) ; off-sheet TA_GPIO1
TA_PORZ: Q1.1(G) R180.1 ; off-sheet TA_PORZ
TA_RESETZ: Q2.1(G) ; off-sheet TA_RESETZ

Not connected (* = marked no-connect by the designer): U33 1(NC)*

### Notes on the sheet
- Push-Buttons
- PORZ Push-Button and Test Automation
- RESETZ Push-Button and Test Automation
- TA Header low enable the p-channel FET, shorting signal to GND.
- INT1 Push-Button and Test Automation

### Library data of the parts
C181 C182 = CMP-0006659-2: as C43 on sheet PROC111_AM263x_7_PRU
Q1-Q3 = CMP-0078819-2: MOSFET, P-CH, -12 V, -4.3 A, SOT-23; Alternate Manufacturer: None; Manufacturer: Infineon Technologies; SizeY_mm: 3; ChMode: Enhancement; SizeX_mm: 2.5; QgTyp_nC: 10; ChType: P; AEC Qualified: N; Value2: 10 nC; SizeZ_mm: 1.1; Green_Lifecycle: Active; Vgs_V: -8V; SizeArea_mm2: 7.5; Value: -12V; IdsMax_A: -4.3A; SizeAreaWB_mm2: 14; AEC Category: Q101; Value1: 0.05 ohm; Rdson45_ohm: 50m; Green_REACh: Passed
R177-R179 R181 = CMP-0026658-1: as R287 on sheet PROC111_AM263x_7_PRU
R180 = CMP-0026992-3: RES, 0, 5%, 0.1 W, AEC-Q200 Grade 0, 0402; Manufacturer: Panasonic; Power_W: 100mW; TempCo: 600 ppm/C; Value_Code: 0000; Value: 0; EIA_Code: E24; SizeX_mm: 1; SizeY_mm: 0.5; SizeZ_mm: 0.6; Value2: 0.1W; AEC Qualified: Y; VDC_V: 50V; AEC Category: Q200; SizeAreaWB_mm2: 3
SW2-SW4 = CMP-0093456-1: Tactile Switch SPST-NO Side Actuated Surface Mount, Right Angle; Manufacturer: Wurth Electronics; Operating Force: 160gf; SizeZ_mm: 1.75mm; AEC Qualified: No; Electromechanical Life: 200000Cycles; VDC_V: 12V; Contact Current Rating: 50mA; Coil Resistance_ohm: 100mΩ
U33 = CMP-0051392-2: Single Buffer/Driver With Open-Drain Output, DCK0005A, SMALL T&R; Manufacturer: Texas Instruments; Input Type: CMOS/TTL; F @ Nom Voltage(Max)(Mhz): 150; Technology Family: LVC; VCC(Min)(V): 1.65; 3-State Output: No; Rating: Catalog; Logic: True; ICC @ Nom Voltage(Max)(mA): 0.01; Bits(#): 1; VCC(Max)(V): 5.5; Sub-Family: Non-Inverting Buffer/Driver; Output Drive (IOL/IOH)(Max)(mA): 32/-32; tpd @ Nom Voltage(Max)(ns): 8.6,6,4.7,4; Output Type: CMOS; Voltage(Nom)(V): 1.8,2.5,3.3,5; AEC Category: Q200; AEC Qualified: N; CompType: IC; SizeAreaWB_mm2: 9.3; SizeArea_mm2: 4.2; SizeX_mm: 2.1; SizeY_mm: 2.0; SizeZ_mm: 1.1
U34 = CMP-0051904-4: Dual Schmitt-Trigger Buffer, DSF0006A, LARGE T&R; Manufacturer: Texas Instruments; Output Type: CMOS; Bits(#): 2; Input Type: CMOS/TTL; Technology Family: LVC; Schmitt Trigger: Yes; 3-State Output: No; VCC(Max)(V): 5.5; Sub-Family: Non-Inverting Buffer/Driver; Rating: Catalog; Output Drive (IOL/IOH)(Max)(mA): 32/-32; ICC @ Nom Voltage(Max)(mA): 0.01; VCC(Min)(V): 1.65; F @ Nom Voltage(Max)(Mhz): 150; Logic: True; Voltage(Nom)(V): 1.8,2.5,3.3,5; tpd @ Nom Voltage(Max)(ns): 9.3,5.7,5.4,4.3

## Sheet PROC111_Test_Automation.SchDoc
size 431 x 279 mm; Date: Not shown in title block; ApprovedBy: Not shown in title block; CheckedBy: Not shown in title block; Author: Not shown in title block; CompanyName: Not shown in title block; Engineer: Not shown in title block; Organization: Not shown in title block; Address1: Not shown in title block; Address2: Not shown in title block; Address3: Not shown in title block; Address4: Not shown in title block; DocumentNumber: 14; Revision: Use project parameter SCH_Rev; SheetNumber: 14; SheetTotal: 24; PageSetup: Record=PageOptions¦CenterHorizontal=True¦CenterVertical=True¦PrintScale=1.00¦XCorrection=1.00¦YCorrection=1.00¦PrintKind=0¦BorderSize=5000000¦LeftOffset=0¦BottomOffset=0¦Orientation=2¦PaperLength=1000¦PaperWidth=1000¦Scale=100¦PaperSource=15¦PrintQuality=600¦MediaType=1¦DitherType=10¦PaperKind=Letter¦PrintScaleMode=1
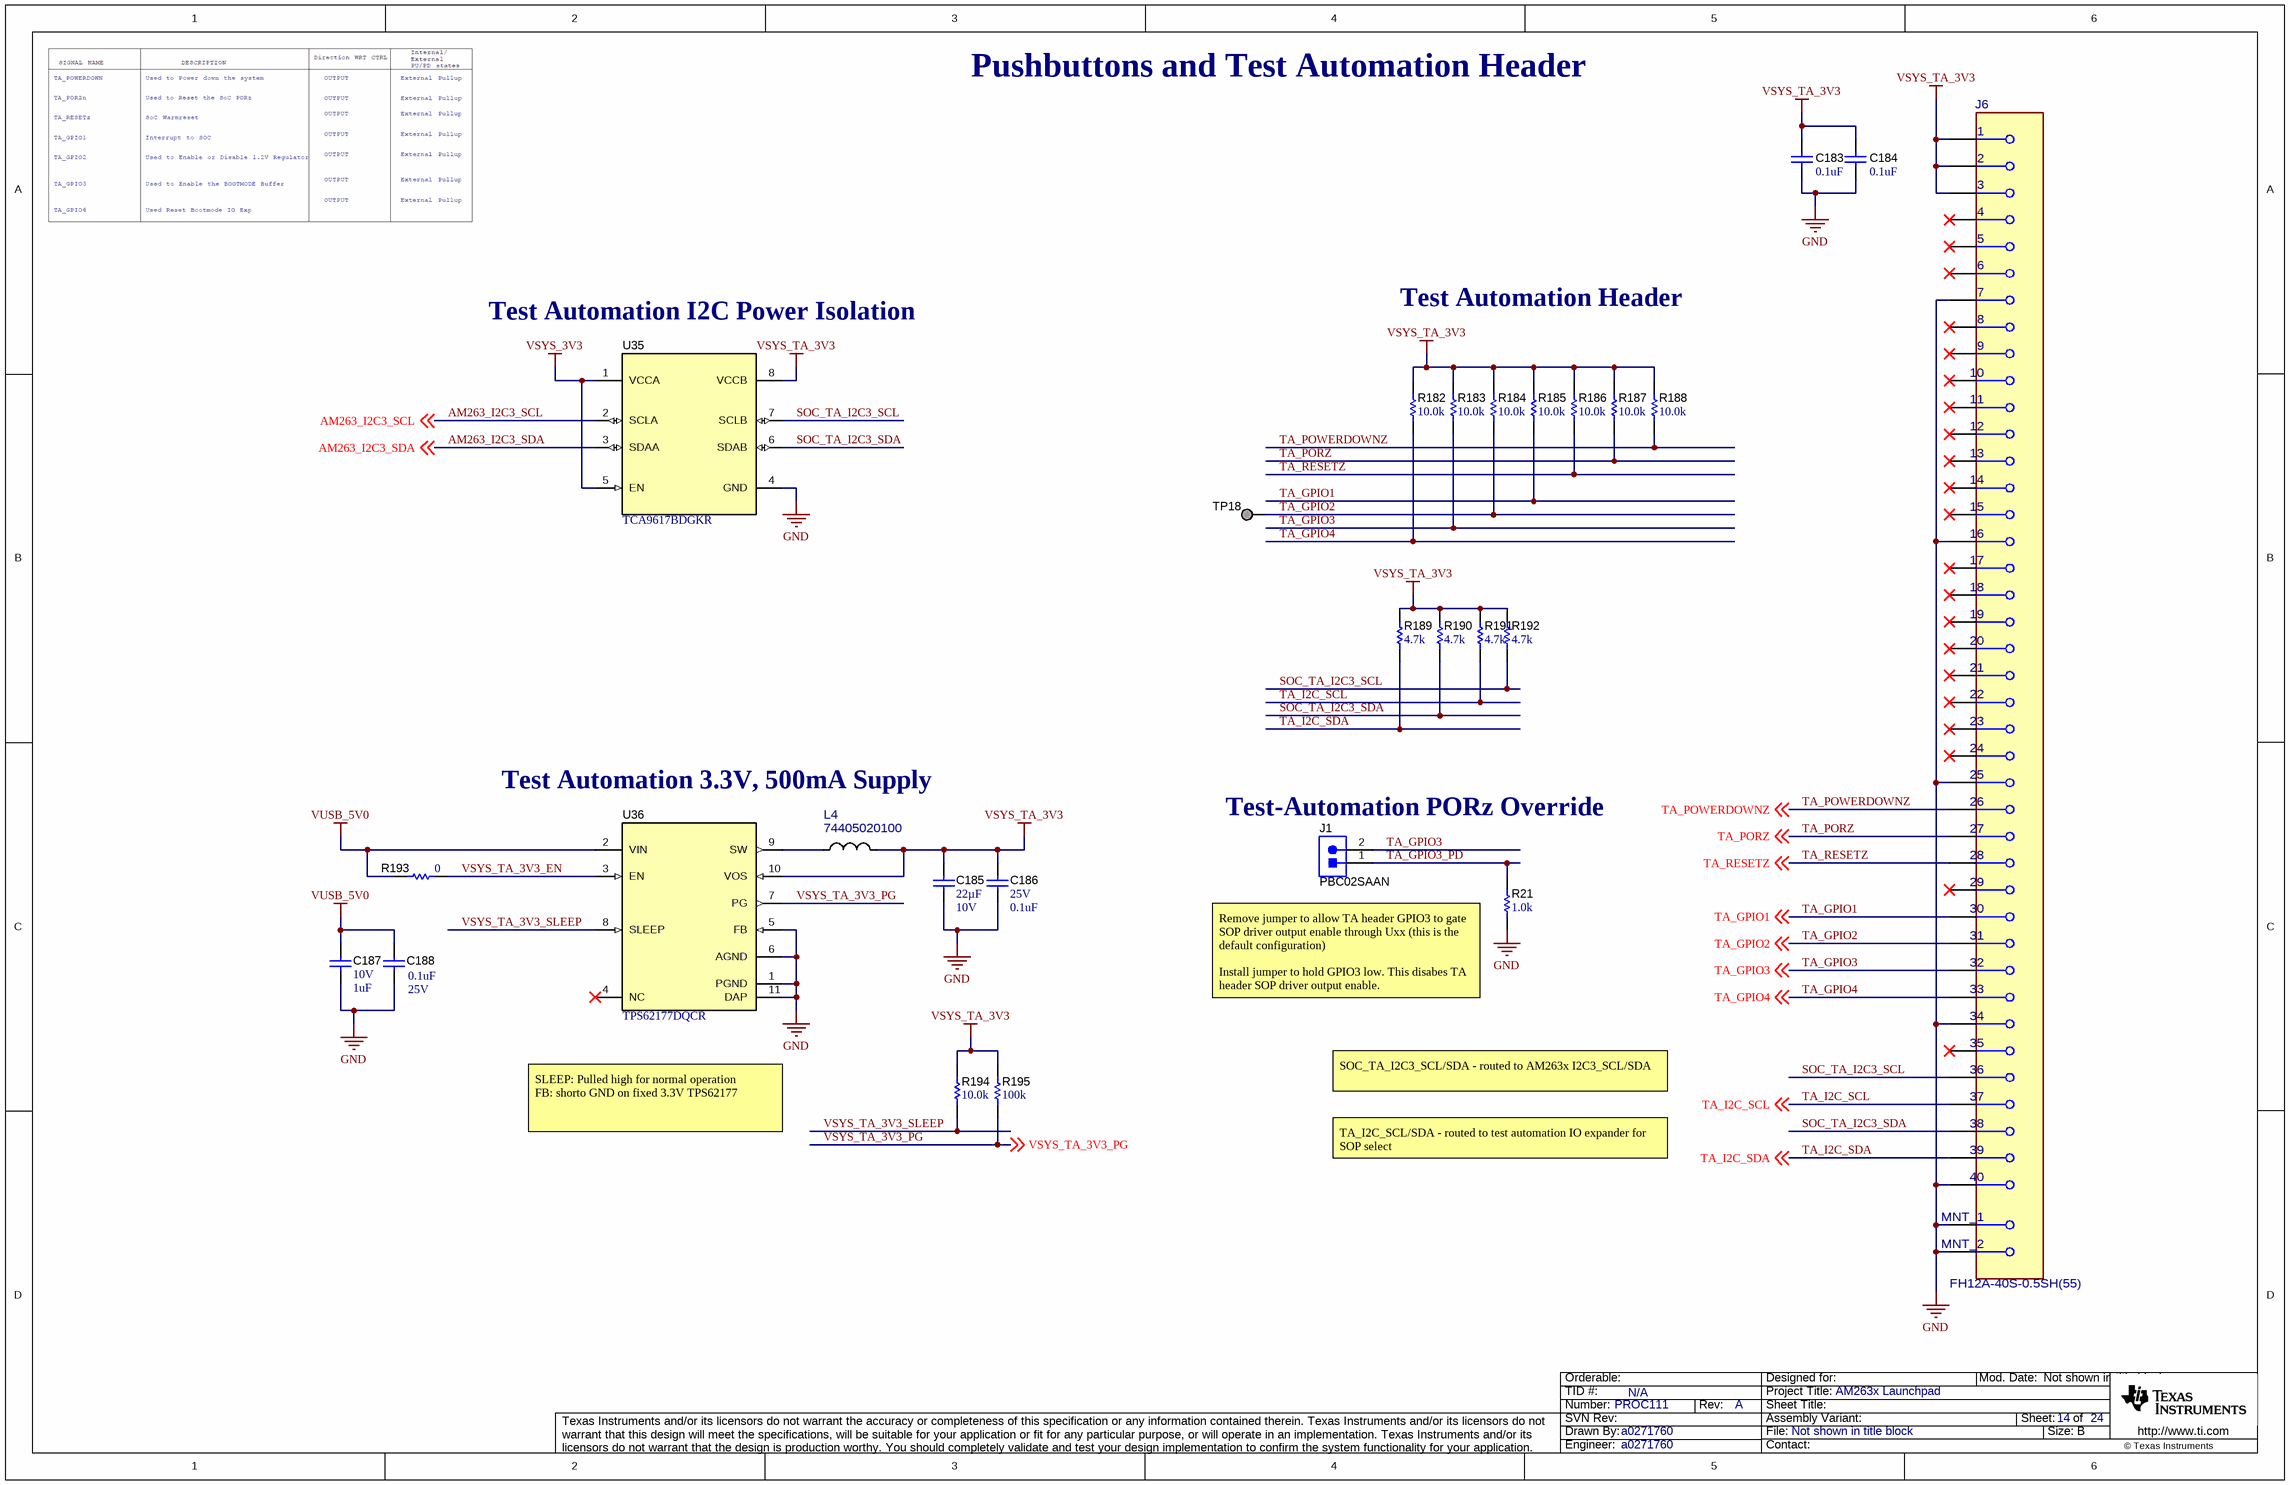
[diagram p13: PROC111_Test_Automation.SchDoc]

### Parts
C183  ValueDisplayed: 0.1uF  [0402]  (hidden comment: GRM155R71E104KE14D)
C184  ValueDisplayed: 0.1uF  [0402]  (hidden comment: GRM155R71E104KE14D)
C185  Cap_F: 22µF  VDC_V: 10V  [0805_HV]  (hidden comment: GRM21BZ71A226ME15L)
C186  VDC_V: 25V  ValueDisplayed: 0.1uF  [0402]  (hidden comment: GRM155R71E104KE14D)
C187  VDC_V: 10V  ValueDisplayed: 1uF  [0402_070]  (hidden comment: GCM155C71A105KE38D)
C188  VDC_V: 25V  ValueDisplayed: 0.1uF  [0402]  (hidden comment: GRM155R71E104KE14D)
J1  PBC02SAAN  [Sullins_PBC02SAAN]
J6  FH12A-40S-0.5SH(55)  [FP-FH12A-40S-0.5SH(55)_FFC40-MFG]
L4  74405020100  [FP-74405020100_SMT_IND_2MM0_1MM6-MFG]
R21  ValueDisplayed: 1.0k  [0402]  (hidden comment: ERJ-2GEJ102X)
R182  ValueDisplayed: 10.0k  [0402]  (hidden comment: ERJ-2RKF1002X)
R183  ValueDisplayed: 10.0k  [0402]  (hidden comment: ERJ-2RKF1002X)
R184  ValueDisplayed: 10.0k  [0402]  (hidden comment: ERJ-2RKF1002X)
R185  ValueDisplayed: 10.0k  [0402]  (hidden comment: ERJ-2RKF1002X)
R186  ValueDisplayed: 10.0k  [0402]  (hidden comment: ERJ-2RKF1002X)
R187  ValueDisplayed: 10.0k  [0402]  (hidden comment: ERJ-2RKF1002X)
R188  ValueDisplayed: 10.0k  [0402]  (hidden comment: ERJ-2RKF1002X)
R189  ValueDisplayed: 4.7k  [0402]  (hidden comment: CRCW04024K70JNED)
R190  ValueDisplayed: 4.7k  [0402]  (hidden comment: CRCW04024K70JNED)
R191  ValueDisplayed: 4.7k  [0402]  (hidden comment: CRCW04024K70JNED)
R192  ValueDisplayed: 4.7k  [0402]  (hidden comment: CRCW04024K70JNED)
R193  ValueDisplayed: 0  [0402L]  (hidden comment: ERJ-2GE0R00X)
R194  ValueDisplayed: 10.0k  [0402]  (hidden comment: ERJ-2RKF1002X)
R195  ValueDisplayed: 100k  [0402]  (hidden comment: ERJ-2RKF1003X)
TP18  TESTPOINT  [TP_25MIL-SMT]  (value not drawn)  (no BOM)
U35  TCA9617BDGKR  [DGK0008A_N]
U36  TPS62177DQCR  [DQC0010A]

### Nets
GND: C183.1 C184.1 C185.2 C186.2 C187.2 C188.2 J6.7 J6.16 J6.25 J6.34 J6.40 J6.41(MNT_1) J6.42(MNT_2) R21.1 U35.4(GND) U36.1(PGND) U36.5(FB) U36.6(AGND) U36.11(DAP)
VSYS_3V3: U35.1(VCCA) U35.5(EN)
VSYS_TA_3V3: C183.2 C184.2 C185.1 C186.1 J6.1 J6.2 J6.3 L4.2 R182.1 R183.1 R184.1 R185.1 R186.1 R187.1 R188.1 R189.2 R190.2 R191.2 R192.2 R194.2 R195.2 U35.8(VCCB) U36.10(VOS)
VUSB_5V0: C187.1 C188.1 R193.2 U36.2(VIN)
AM263_I2C3_SCL: U35.2(SCLA) ; off-sheet AM263_I2C3_SCL
AM263_I2C3_SDA: U35.3(SDAA) ; off-sheet AM263_I2C3_SDA
SOC_TA_I2C3_SCL: J6.36 R192.1 U35.7(SCLB)
SOC_TA_I2C3_SDA: J6.38 R190.1 U35.6(SDAB)
TA_GPIO1: J6.30 R185.2 ; off-sheet TA_GPIO1
TA_GPIO2: J6.31 R184.2 TP18.1 ; off-sheet TA_GPIO2
TA_GPIO3: J1.2 J6.32 R183.2 ; off-sheet TA_GPIO3
TA_GPIO3_PD: J1.1 R21.2
TA_GPIO4: J6.33 R182.2 ; off-sheet TA_GPIO4
TA_I2C_SCL: J6.37 R191.1 ; off-sheet TA_I2C_SCL
TA_I2C_SDA: J6.39 R189.1 ; off-sheet TA_I2C_SDA
TA_PORZ: J6.27 R187.2 ; off-sheet TA_PORZ
TA_POWERDOWNZ: J6.26 R188.2 ; off-sheet TA_POWERDOWNZ
TA_RESETZ: J6.28 R186.2 ; off-sheet TA_RESETZ
VSYS_TA_3V3_EN: R193.1 U36.3(EN)
VSYS_TA_3V3_PG: R195.1 U36.7(PG) ; off-sheet VSYS_TA_3V3_PG
VSYS_TA_3V3_SLEEP: R194.1 U36.8(SLEEP)
NetL4_1: L4.1 U36.9(SW)

Not connected (* = marked no-connect by the designer): J6 4* 5* 6* 8* 9* 10* 11* 12* 13* 14* 15* 17* 18* 19* 20* 21* 22* 23* 24* 29* 35*; U36 4(NC)*

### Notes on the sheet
- Pushbuttons and Test Automation Header
- Test Automation I2C Power Isolation
- Test Automation Header
- Test Automation 3.3V, 500mA Supply
- (near J1) Test-Automation PORz Override
- Remove jumper to allow TA header GPIO3 to gate SOP driver output enable through Uxx (this is the default configuration)
  Install jumper to hold GPIO3 low. This disabes TA header SOP driver output enable.
- SOC_TA_I2C3_SCL/SDA - routed to AM263x I2C3_SCL/SDA
- SLEEP: Pulled high for normal operation
  FB: shorto GND on fixed 3.3V TPS62177
- TA_I2C_SCL/SDA - routed to test automation IO expander for SOP select

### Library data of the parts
C183 C184 = CMP-0006659-2: as C43 on sheet PROC111_AM263x_7_PRU
C185 = CMP-0008377-2: CAP, CERM, 22 uF, 10 V, +/- 20%, X7R, 0805; Manufacturer: MuRata; SizeY_mm: 1.25; Cap_Case: 0805; SizeArea_mm2: 2.5; AEC Qualified: N; AEC Category: Q200; ValueDisplayed: 22uF; TaMin_C: -55°C; SizeAreaWB_mm2: 6.75; Value1: Unknown; U/M: EA; Value: 22uF; TaMax_C: 125°C; SizeZ_mm: 1.45; SizeX_mm: 2
C186 C188 = CMP-0006659-2: CAP, CERM, 0.1 uF, 25 V, +/- 10%, X7R, 0402; Manufacturer: MuRata; TaMin_C: -55°C; Polarized: N; SizeAreaWB_mm2: 3; Value1: Unknown; U/M: EA; Value: 0.1uF; TaMax_C: 125°C; SizeZ_mm: 0.6; SizeX_mm: 1; SizeY_mm: 0.5; Cap_F: 100nF; AEC Category: Q200
C187 = CMP-0006349-2: CAP, CERM, 1 uF, 10 V, +/- 10%, X7S, AEC-Q200 Grade 1, 0402; Manufacturer: MuRata; TaMin_C: -55°C; Polarized: N; SizeAreaWB_mm2: 3; Value1: Unknown; U/M: EA; Value: 1uF; TaMax_C: 125°C; SizeZ_mm: 0.7; SizeX_mm: 1; SizeY_mm: 0.5; Cap_Case: 0402; AEC Qualified: Y; Cap_F: 1µF; AEC Category: Q200
J1 = CMP-0054566-1: Header, 100mil, 2x1, Gold, TH; Manufacturer: Sullins Connector Solutions; CNHeader: TRUE; Current_A: 3A; Green_Lifecycle: Active; Shrouded: N; Gender: Male; Green_REACh: Passed; Voltage_V: 1.8kV; Row_Count: 1; Pitch_mm: 2.54; CT: FALSE; Cert_UL: Y
J6 = CMP-0093156-1: Manufacturer: Hirose; Is Female: yes; ContactFinish: Gold,Nickel; Current_A: 500mA; DUT-Pitch_mm: 0.5mm; Voltage_V: 50V; SizeZ_mm: 3.6mm; Conn Gender: Female; Conn Orientation: Horizontal; AEC Qualified: No
L4 = CMP-0078538-1: 10µH Semi-Shielded Wirewound Inductor 580mA 816 mOhm Max Nonstandard; Manufacturer: Wurth Electronics; Symbol Name: SYM-74405020100; Material: Ferrite; SizeZ_mm: 1mm; Isat: 0.95A; AEC Qualified: No; Irms: 0.58A
R21 = CMP-0078193-1: as R96 on sheet PROC111_AM263x_7_PRU
R182-R188 R194 = CMP-0026658-1: as R287 on sheet PROC111_AM263x_7_PRU
R189-R192 = CMP-0026938-5: as R73 on sheet PROC111_AM263x_7_PRU
R193 = CMP-0026992-3: as R180 on sheet PROC111_Push_Buttons
R195 = CMP-0026659-2: RES, 100 k, 1%, 0.1 W, 0402; Manufacturer: Panasonic; U/M: EA; Value2: 0.1W; EIA_Code: E96; Value: 100k; SizeArea_mm2: 0.5; TempCo: 100 ppm/C; SizeZ_mm: 0.6; AEC Category: Q200; VDC_V: 50V; Power_W: 100mW; AEC Grade: 0; SizeX_mm: 1; AEC Qualified: Yes
TP18 = CMP-0078143-3: TEST POINT.  No entry in BOM.
U35 = CMP-0076016-2: Level-Translating I2C Bus Repeater, DGK0008A (VSSOP-8); Manufacturer: Texas Instruments; SizeAreaWB_mm2: 23.6; SizeArea_mm2: 14.7; SizeZ_mm: 1.1; SizeY_mm: 3; CompType: IC; SizeX_mm: 4.9; AEC Category: Q200; AEC Qualified: N
U36 = CMP-0067107-3: 28V, 0.5A Step-Down Converter with SNOOZE Mode, DQC0010A (WSON-10); Alternate PartNumber: TPS62177DQCT; Manufacturer: Texas Instruments; SizeZ_mm: 0.8; SizeX_mm: 2.0; SizeY_mm: 3.0; SizeArea_mm2: 6.0; CompType: IC; SizeAreaWB_mm2: 12.0

## Sheet PROC111_Ehernet_PHY_1.SchDoc
size 431 x 279 mm; Date: Not shown in title block; ApprovedBy: Not shown in title block; CheckedBy: Not shown in title block; Author: Not shown in title block; CompanyName: Not shown in title block; Engineer: Not shown in title block; Organization: Not shown in title block; Address1: Not shown in title block; Address2: Not shown in title block; Address3: Not shown in title block; Address4: Not shown in title block; DocumentNumber: 15; Revision: Use project parameter SCH_Rev; SheetNumber: 15; SheetTotal: 24; PageSetup: Record=PageOptions¦CenterHorizontal=True¦CenterVertical=True¦PrintScale=1.00¦XCorrection=1.00¦YCorrection=1.00¦PrintKind=0¦BorderSize=5000000¦LeftOffset=0¦BottomOffset=0¦Orientation=2¦PaperLength=1000¦PaperWidth=1000¦Scale=100¦PaperSource=15¦PrintQuality=600¦MediaType=1¦DitherType=10¦PaperKind=Letter¦PrintScaleMode=1
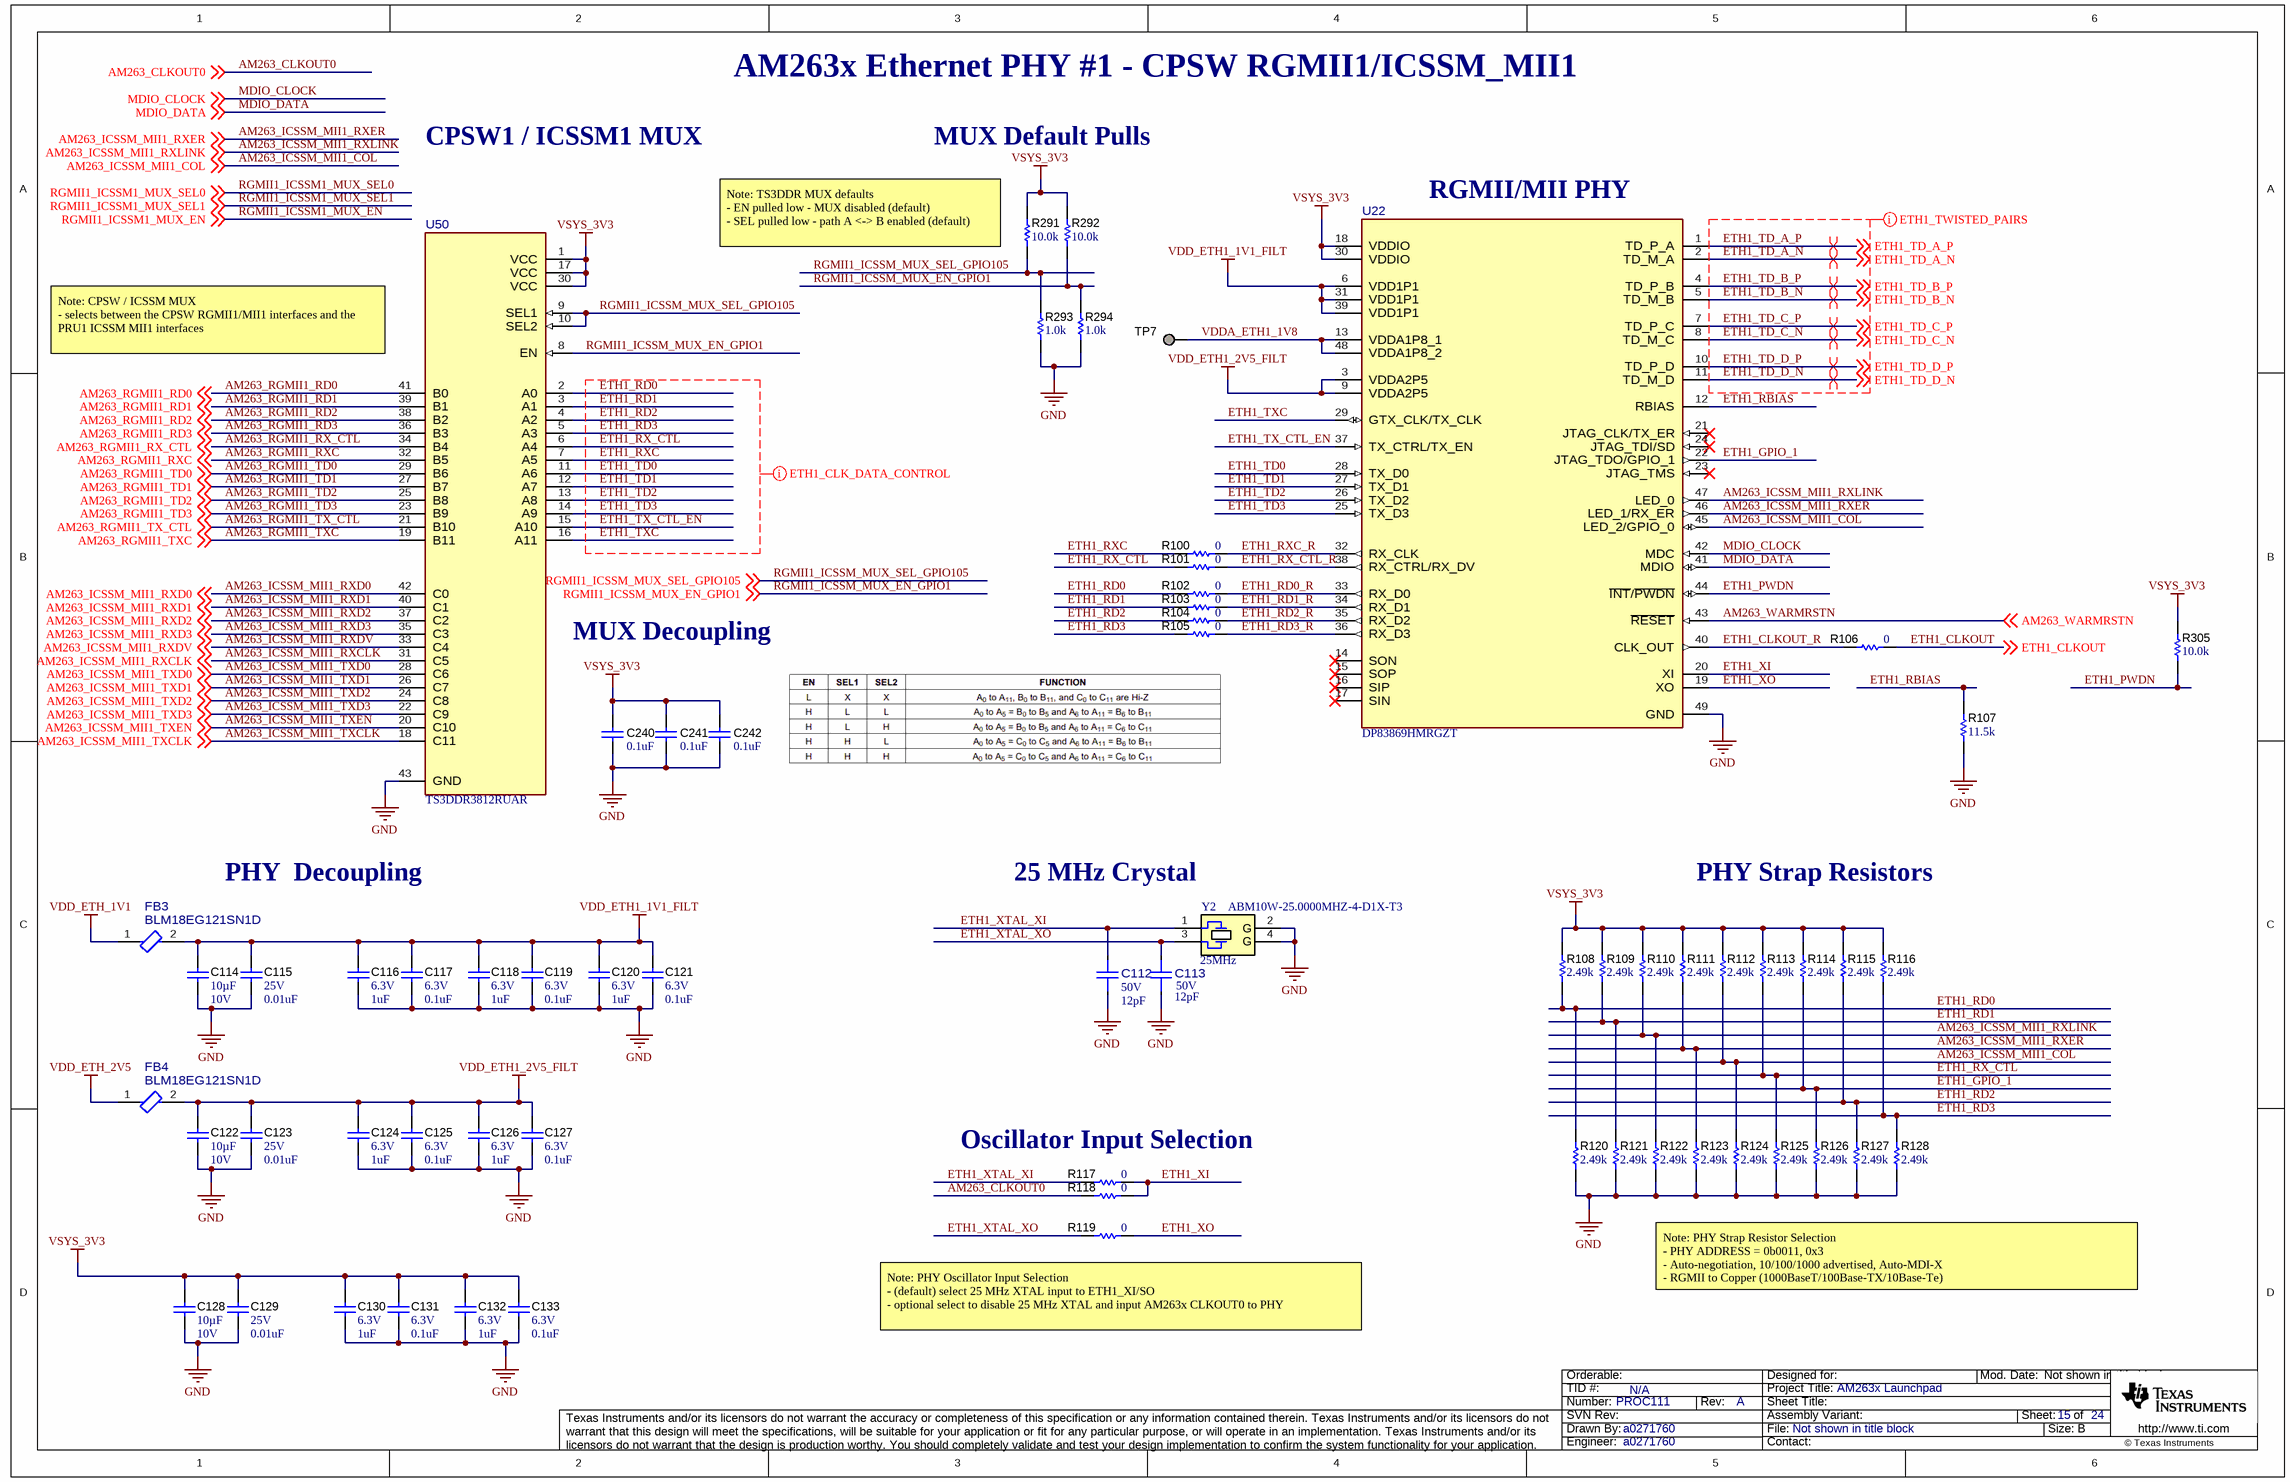
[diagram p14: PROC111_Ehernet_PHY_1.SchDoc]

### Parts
C112  VDC_V: 50V  ValueDisplayed: 12pF  [FP-GRT1555C1H120JA02D_0402-MFG]  (hidden comment: GRT1555C1H120JA02D)
C113  VDC_V: 50V  ValueDisplayed: 12pF  [FP-GRT1555C1H120JA02D_0402-MFG]  (hidden comment: GRT1555C1H120JA02D)
C114  Cap_F: 10µF  VDC_V: 10V  [0603]  (hidden comment: GRM188Z71A106MA73D)
C115  VDC_V: 25V  ValueDisplayed: 0.01uF  [0402]  (hidden comment: GRM155R71E103KA01D)
C116  VDC_V: 6.3V  ValueDisplayed: 1uF  [0402]  (hidden comment: GRM155R70J105MA12D)
C117  VDC_V: 6.3V  ValueDisplayed: 0.1uF  [0402]  (hidden comment: GRM155R70J104KA01D)
C118  VDC_V: 6.3V  ValueDisplayed: 1uF  [0402]  (hidden comment: GRM155R70J105MA12D)
C119  VDC_V: 6.3V  ValueDisplayed: 0.1uF  [0402]  (hidden comment: GRM155R70J104KA01D)
C120  VDC_V: 6.3V  ValueDisplayed: 1uF  [0402]  (hidden comment: GRM155R70J105MA12D)
C121  VDC_V: 6.3V  ValueDisplayed: 0.1uF  [0402]  (hidden comment: GRM155R70J104KA01D)
C122  Cap_F: 10µF  VDC_V: 10V  [0603]  (hidden comment: GRM188Z71A106MA73D)
C123  VDC_V: 25V  ValueDisplayed: 0.01uF  [0402]  (hidden comment: GRM155R71E103KA01D)
C124  VDC_V: 6.3V  ValueDisplayed: 1uF  [0402]  (hidden comment: GRM155R70J105MA12D)
C125  VDC_V: 6.3V  ValueDisplayed: 0.1uF  [0402]  (hidden comment: GRM155R70J104KA01D)
C126  VDC_V: 6.3V  ValueDisplayed: 1uF  [0402]  (hidden comment: GRM155R70J105MA12D)
C127  VDC_V: 6.3V  ValueDisplayed: 0.1uF  [0402]  (hidden comment: GRM155R70J104KA01D)
C128  Cap_F: 10µF  VDC_V: 10V  [0603]  (hidden comment: GRM188Z71A106MA73D)
C129  VDC_V: 25V  ValueDisplayed: 0.01uF  [0402]  (hidden comment: GRM155R71E103KA01D)
C130  VDC_V: 6.3V  ValueDisplayed: 1uF  [0402]  (hidden comment: GRM155R70J105MA12D)
C131  VDC_V: 6.3V  ValueDisplayed: 0.1uF  [0402]  (hidden comment: GRM155R70J104KA01D)
C132  VDC_V: 6.3V  ValueDisplayed: 1uF  [0402]  (hidden comment: GRM155R70J105MA12D)
C133  VDC_V: 6.3V  ValueDisplayed: 0.1uF  [0402]  (hidden comment: GRM155R70J104KA01D)
C240  ValueDisplayed: 0.1uF  [0402]  (hidden comment: GRM155R71E104KE14D)
C241  ValueDisplayed: 0.1uF  [0402]  (hidden comment: GRM155R71E104KE14D)
C242  ValueDisplayed: 0.1uF  [0402]  (hidden comment: GRM155R71E104KE14D)
FB3  BLM18EG121SN1D  [FP-BLM18EG121SN1D_0603-MFG]
FB4  BLM18EG121SN1D  [FP-BLM18EG121SN1D_0603-MFG]
R100  ValueDisplayed: 0  [0402]  (hidden comment: ERJ-2GE0R00X)
R101  ValueDisplayed: 0  [0402]  (hidden comment: ERJ-2GE0R00X)
R102  ValueDisplayed: 0  [0402]  (hidden comment: ERJ-2GE0R00X)
R103  ValueDisplayed: 0  [0402]  (hidden comment: ERJ-2GE0R00X)
R104  ValueDisplayed: 0  [0402]  (hidden comment: ERJ-2GE0R00X)
R105  ValueDisplayed: 0  [0402]  (hidden comment: ERJ-2GE0R00X)
R106  ValueDisplayed: 0  [0402]  (hidden comment: ERJ-2GE0R00X)
R107  ValueDisplayed: 11.5k  [0402]  (hidden comment: ERJ-2RKF1152X)
R108  ValueDisplayed: 2.49k  [0402]  (hidden comment: CRCW04022K49FKED)
R109  ValueDisplayed: 2.49k  [0402]  (hidden comment: CRCW04022K49FKED)
R110  ValueDisplayed: 2.49k  [0402]  (hidden comment: CRCW04022K49FKED)
R111  ValueDisplayed: 2.49k  [0402]  (hidden comment: CRCW04022K49FKED)
R112  ValueDisplayed: 2.49k  [0402]  (hidden comment: CRCW04022K49FKED)
R113  ValueDisplayed: 2.49k  [0402]  (hidden comment: CRCW04022K49FKED)
R114  ValueDisplayed: 2.49k  [0402]  (hidden comment: CRCW04022K49FKED)
R115  ValueDisplayed: 2.49k  [0402]  (hidden comment: CRCW04022K49FKED)
R116  ValueDisplayed: 2.49k  [0402]  (hidden comment: CRCW04022K49FKED)
R117  ValueDisplayed: 0  [0402]  (hidden comment: ERJ-2GE0R00X)
R118  ValueDisplayed: 0  [0402]  (hidden comment: ERJ-2GE0R00X)
R119  ValueDisplayed: 0  [0402]  (hidden comment: ERJ-2GE0R00X)
R120  ValueDisplayed: 2.49k  [0402]  (hidden comment: CRCW04022K49FKED)
R121  ValueDisplayed: 2.49k  [0402]  (hidden comment: CRCW04022K49FKED)
R122  ValueDisplayed: 2.49k  [0402]  (hidden comment: CRCW04022K49FKED)
R123  ValueDisplayed: 2.49k  [0402]  (hidden comment: CRCW04022K49FKED)
R124  ValueDisplayed: 2.49k  [0402]  (hidden comment: CRCW04022K49FKED)
R125  ValueDisplayed: 2.49k  [0402]  (hidden comment: CRCW04022K49FKED)
R126  ValueDisplayed: 2.49k  [0402]  (hidden comment: CRCW04022K49FKED)
R127  ValueDisplayed: 2.49k  [0402]  (hidden comment: CRCW04022K49FKED)
R128  ValueDisplayed: 2.49k  [0402]  (hidden comment: CRCW04022K49FKED)
R291  ValueDisplayed: 10.0k  [0402]  (hidden comment: ERJ-2RKF1002X)
R292  ValueDisplayed: 10.0k  [0402]  (hidden comment: ERJ-2RKF1002X)
R293  ValueDisplayed: 1.0k  [0402]  (hidden comment: ERJ-2GEJ102X)
R294  ValueDisplayed: 1.0k  [0402]  (hidden comment: ERJ-2GEJ102X)
R305  ValueDisplayed: 10.0k  [0402]  (hidden comment: ERJ-2RKF1002X)
TP7  TESTPOINT  [TP_25MIL-SMT]  (value not drawn)  (no BOM)
U22  DP83869HMRGZT  [RGZ0048B-MFG]
U50  TS3DDR3812RUAR  [RUA0042A-MFG]
Y2  Frequency_Fixed: 25MHz  [Abracon_ABM10W]  (hidden comment: ABM10W-25.0000MHZ-4-D1X-T3)

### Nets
GND: C112.1 C113.1 C114.2 C115.2 C116.2 C117.2 C118.2 C119.2 C120.2 C121.2 C122.2 C123.2 C124.2 C125.2 C126.2 C127.2 C128.2 C129.2 C130.2 C131.2 C132.2 C133.2 C240.1 C241.1 C242.1 R107.1 R120.1 R121.1 R122.1 R123.1 R124.1 R125.1 R126.1 R127.1 R128.1 R293.1 R294.1 U22.49(GND) U50.43(GND) Y2.2(GND) Y2.4(GND)
VDD_ETH1_1V1_FILT: C114.1 C115.1 C116.1 C117.1 C118.1 C119.1 C120.1 C121.1 FB3.2 U22.6(VDD1P1) U22.31(VDD1P1) U22.39(VDD1P1)
VDD_ETH1_2V5_FILT: C122.1 C123.1 C124.1 C125.1 C126.1 C127.1 FB4.2 U22.3(VDDA2P5) U22.9(VDDA2P5)
VDD_ETH_1V1: FB3.1
VDD_ETH_2V5: FB4.1
VSYS_3V3: C128.1 C129.1 C130.1 C131.1 C132.1 C133.1 C240.2 C241.2 C242.2 R108.2 R109.2 R110.2 R111.2 R112.2 R113.2 R114.2 R115.2 R116.2 R291.1 R292.1 R305.1 U22.18(VDDIO) U22.30(VDDIO) U50.1(VCC) U50.17(VCC) U50.30(VCC)
AM263_CLKOUT0: R118.1 ; off-sheet AM263_CLKOUT0
AM263_ICSSM_MII1_COL: R112.1 R124.2 U22.45(LED_2/GPIO_0) ; off-sheet AM263_ICSSM_MII1_COL
AM263_ICSSM_MII1_RXCLK: U50.31(C5) ; off-sheet AM263_ICSSM_MII1_RXCLK
AM263_ICSSM_MII1_RXD0: U50.42(C0) ; off-sheet AM263_ICSSM_MII1_RXD0
AM263_ICSSM_MII1_RXD1: U50.40(C1) ; off-sheet AM263_ICSSM_MII1_RXD1
AM263_ICSSM_MII1_RXD2: U50.37(C2) ; off-sheet AM263_ICSSM_MII1_RXD2
AM263_ICSSM_MII1_RXD3: U50.35(C3) ; off-sheet AM263_ICSSM_MII1_RXD3
AM263_ICSSM_MII1_RXDV: U50.33(C4) ; off-sheet AM263_ICSSM_MII1_RXDV
AM263_ICSSM_MII1_RXER: R111.1 R123.2 U22.46(LED_1/RX_ER) ; off-sheet AM263_ICSSM_MII1_RXER
AM263_ICSSM_MII1_RXLINK: R110.1 R122.2 U22.47(LED_0) ; off-sheet AM263_ICSSM_MII1_RXLINK
AM263_ICSSM_MII1_TXCLK: U50.18(C11) ; off-sheet AM263_ICSSM_MII1_TXCLK
AM263_ICSSM_MII1_TXD0: U50.28(C6) ; off-sheet AM263_ICSSM_MII1_TXD0
AM263_ICSSM_MII1_TXD1: U50.26(C7) ; off-sheet AM263_ICSSM_MII1_TXD1
AM263_ICSSM_MII1_TXD2: U50.24(C8) ; off-sheet AM263_ICSSM_MII1_TXD2
AM263_ICSSM_MII1_TXD3: U50.22(C9) ; off-sheet AM263_ICSSM_MII1_TXD3
AM263_ICSSM_MII1_TXEN: U50.20(C10) ; off-sheet AM263_ICSSM_MII1_TXEN
AM263_RGMII1_RD0: U50.41(B0) ; off-sheet AM263_RGMII1_RD0
AM263_RGMII1_RD1: U50.39(B1) ; off-sheet AM263_RGMII1_RD1
AM263_RGMII1_RD2: U50.38(B2) ; off-sheet AM263_RGMII1_RD2
AM263_RGMII1_RD3: U50.36(B3) ; off-sheet AM263_RGMII1_RD3
AM263_RGMII1_RX_CTL: U50.34(B4) ; off-sheet AM263_RGMII1_RX_CTL
AM263_RGMII1_RXC: U50.32(B5) ; off-sheet AM263_RGMII1_RXC
AM263_RGMII1_TD0: U50.29(B6) ; off-sheet AM263_RGMII1_TD0
AM263_RGMII1_TD1: U50.27(B7) ; off-sheet AM263_RGMII1_TD1
AM263_RGMII1_TD2: U50.25(B8) ; off-sheet AM263_RGMII1_TD2
AM263_RGMII1_TD3: U50.23(B9) ; off-sheet AM263_RGMII1_TD3
AM263_RGMII1_TX_CTL: U50.21(B10) ; off-sheet AM263_RGMII1_TX_CTL
AM263_RGMII1_TXC: U50.19(B11) ; off-sheet AM263_RGMII1_TXC
AM263_WARMRSTN: U22.43(~{RESET}) ; off-sheet AM263_WARMRSTN
ETH1_CLKOUT: R106.2 ; off-sheet ETH1_CLKOUT
ETH1_CLKOUT_R: R106.1 U22.40(CLK_OUT)
ETH1_GPIO_1: R114.1 R126.2 U22.22(JTAG_TDO/GPIO_1)
ETH1_PWDN: R305.2 U22.44(~{INT}/~{PWDN})
ETH1_RBIAS: R107.2 U22.12(RBIAS)
ETH1_RD0: R102.1 R108.1 R120.2 U50.2(A0)
ETH1_RD0_R: R102.2 U22.33(RX_D0)
ETH1_RD1: R103.1 R109.1 R121.2 U50.3(A1)
ETH1_RD1_R: R103.2 U22.34(RX_D1)
ETH1_RD2: R104.1 R115.1 R127.2 U50.4(A2)
ETH1_RD2_R: R104.2 U22.35(RX_D2)
ETH1_RD3: R105.1 R116.1 R128.2 U50.5(A3)
ETH1_RD3_R: R105.2 U22.36(RX_D3)
ETH1_RX_CTL: R101.1 R113.1 R125.2 U50.6(A4)
ETH1_RX_CTL_R: R101.2 U22.38(RX_CTRL/RX_DV)
ETH1_RXC: R100.1 U50.7(A5)
ETH1_RXC_R: R100.2 U22.32(RX_CLK)
ETH1_TD0: U22.28(TX_D0) U50.11(A6)
ETH1_TD1: U22.27(TX_D1) U50.12(A7)
ETH1_TD2: U22.26(TX_D2) U50.13(A8)
ETH1_TD3: U22.25(TX_D3) U50.14(A9)
ETH1_TD_A_N: U22.2(TD_M_A) ; off-sheet ETH1_TD_A_N
ETH1_TD_A_P: U22.1(TD_P_A) ; off-sheet ETH1_TD_A_P
ETH1_TD_B_N: U22.5(TD_M_B) ; off-sheet ETH1_TD_B_N
ETH1_TD_B_P: U22.4(TD_P_B) ; off-sheet ETH1_TD_B_P
ETH1_TD_C_N: U22.8(TD_M_C) ; off-sheet ETH1_TD_C_N
ETH1_TD_C_P: U22.7(TD_P_C) ; off-sheet ETH1_TD_C_P
ETH1_TD_D_N: U22.11(TD_M_D) ; off-sheet ETH1_TD_D_N
ETH1_TD_D_P: U22.10(TD_P_D) ; off-sheet ETH1_TD_D_P
ETH1_TX_CTL_EN: U22.37(TX_CTRL/TX_EN) U50.15(A10)
ETH1_TXC: U22.29(GTX_CLK/TX_CLK) U50.16(A11)
ETH1_XI: R117.2 R118.2 U22.20(XI)
ETH1_XO: R119.2 U22.19(XO)
ETH1_XTAL_XI: C112.2 R117.1 Y2.1
ETH1_XTAL_XO: C113.2 R119.1 Y2.3
MDIO_CLOCK: U22.42(MDC) ; off-sheet MDIO_CLOCK
MDIO_DATA: U22.41(MDIO) ; off-sheet MDIO_DATA
RGMII1_ICSSM_MUX_EN_GPIO1: R292.2 R294.2 U50.8(EN) ; off-sheet RGMII1_ICSSM_MUX_EN_GPIO1
RGMII1_ICSSM_MUX_SEL_GPIO105: R291.2 R293.2 U50.9(SEL1) U50.10(SEL2) ; off-sheet RGMII1_ICSSM_MUX_SEL_GPIO105
VDDA_ETH1_1V8: TP7.1 U22.13(VDDA1P8_1) U22.48(VDDA1P8_2)

Not connected (* = marked no-connect by the designer): U22 14(SON)* 15(SOP)* 16(SIP)* 17(SIN)* 21(JTAG_CLK/TX_ER)* 23(JTAG_TMS)* 24(JTAG_TDI/SD)*

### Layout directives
differential pair: ETH1_TD_A_N, ETH1_TD_A_P, ETH1_TD_B_N, ETH1_TD_B_P, ETH1_TD_C_N, ETH1_TD_C_P, ETH1_TD_D_N, ETH1_TD_D_P
mark named ETH1_TWISTED_PAIRS: ETH1_TD_A_N, ETH1_TD_A_P, ETH1_TD_B_N, ETH1_TD_B_P, ETH1_TD_C_N, ETH1_TD_C_P, ETH1_TD_D_N, ETH1_TD_D_P
mark named ETH1_CLK_DATA_CONTROL: ETH1_RD0, ETH1_RD1, ETH1_RD2, ETH1_RD3, ETH1_RX_CTL, ETH1_RXC, ETH1_TD0, ETH1_TD1, ETH1_TD2, ETH1_TD3, ETH1_TX_CTL_EN, ETH1_TXC

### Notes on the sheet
- AM263x Ethernet PHY #1 - CPSW RGMII1/ICSSM_MII1
- CPSW1 / ICSSM1 MUX
- MUX Default Pulls
- (near U22) RGMII/MII PHY
- (near R291) Note: TS3DDR MUX defaults
  - EN pulled low - MUX disabled (default)
  - SEL pulled low - path A <-> B enabled (default)
- (near U50) Note: CPSW / ICSSM MUX
  - selects between the CPSW RGMII1/MII1 interfaces and the PRU1 ICSSM MII1 interfaces
- (near U50) MUX Decoupling
- PHY  Decoupling
- (near Y2) 25 MHz Crystal
- PHY Strap Resistors
- Oscillator Input Selection
- Note: PHY Strap Resistor Selection
  - PHY ADDRESS = 0b0011, 0x3
  - Auto-negotiation, 10/100/1000 advertised, Auto-MDI-X
  - RGMII to Copper (1000BaseT/100Base-TX/10Base-Te)
- (near R119) Note: PHY Oscillator Input Selection
  - (default) select 25 MHz XTAL input to ETH1_XI/SO
  - optional select to disable 25 MHz XTAL and input AM263x CLKOUT0 to PHY

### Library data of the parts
C112 C113 = CMP-0120209-1: Multi-Layer Ceramic Capacitor 12pF 50V C0G ±5% 0402 Paper T/R; Manufacturer: Murata; TempCo: 30ppm/°C; SizeZ_mm: 0.55mm; AEC Qualified: Yes; AEC Grade: Grade 1
C114 C122 C128 = CMP-0007497-5: CAP, CERM, 10 uF, 10 V, +/- 20%, X7R, 0603; Manufacturer: MuRata; TaMin_C: -55°C; Polarized: N; SizeAreaWB_mm2: 4.68; Value1: Unknown; U/M: EA; Value: 10uF; TaMax_C: 125°C; SizeZ_mm: 1; SizeX_mm: 1.6; SizeY_mm: 0.8; SizeArea_mm2: 1.28; AEC Category: Q200
C115 C123 C129 = CMP-0006658-2: CAP, CERM, 0.01 uF, 25 V, +/- 10%, X7R, 0402; Manufacturer: MuRata; TaMin_C: -55°C; Polarized: N; SizeAreaWB_mm2: 3; Value1: Unknown; U/M: EA; Value: 0.01uF; TaMax_C: 125°C; SizeZ_mm: 0.6; SizeX_mm: 1; SizeY_mm: 0.5; Cap_F: 10nF; AEC Category: Q200
C116 C118 C120 C124 C126 C130 C132 = CMP-0006624-2: CAP, CERM, 1 uF, 6.3 V, +/- 20%, X7R, 0402; Manufacturer: MuRata; TaMin_C: -55°C; Polarized: N; SizeAreaWB_mm2: 3; Value1: Unknown; U/M: EA; Value: 1uF; TaMax_C: 125°C; SizeZ_mm: 0.6; SizeX_mm: 1; SizeY_mm: 0.5; Cap_F: 1µF; AEC Category: Q200
C117 C119 C121 C125 C127 C131 C133 = CMP-0006623-2: CAP, CERM, 0.1 uF, 6.3 V, +/- 10%, X7R, 0402; Manufacturer: MuRata; TaMin_C: -55°C; Polarized: N; SizeAreaWB_mm2: 3; Value1: Unknown; U/M: EA; Value: 0.1uF; TaMax_C: 125°C; SizeZ_mm: 0.6; SizeX_mm: 1; SizeY_mm: 0.5; Cap_F: 100nF; AEC Category: Q200
C240-C242 = CMP-0006659-2: as C43 on sheet PROC111_AM263x_7_PRU
FB3 FB4 = CMP-0089199-1: 120 Ohms @ 100MHz 1  Ferrite Bead 0603 (1608 Metric) 2A 40mOhm; Manufacturer: Murata; DCR_ohm: 60m; AEC Qualified: No; Tolerance_%: 25%; SizeZ_mm: 0.95mm; Impedance At Frequency: 120Ω @ 100MHz
R100-R106 R117-R119 = CMP-0026992-3: as R180 on sheet PROC111_Push_Buttons
R107 = CMP-0082348-1: RES, 11.5 k, 1%, 0.1 W, AEC-Q200 Grade 0, 0402; Manufacturer: Panasonic; Value_Code: 11k5; SizeAreaWB_mm2: 3; SizeArea_mm2: 0.5; AEC Qualified: Y; AEC Category: Q200; Value: 11.5k; SizeZ_mm: 0.6; EIA_Code: E96; TempCo: 100 ppm/C; AEC Grade: 0; Power_W: 100mW; Value2: 0.1W; SizeX_mm: 1
R108-R116 R120-R128 = CMP-0026237-2: RES, 2.49 k, 1%, 0.063 W, AEC-Q200 Grade 0, 0402; Manufacturer: Vishay-Dale; Power_W: 63mW; TempCo: 100 ppm/C; Value_Code: 2k49; Value: 2.49k; EIA_Code: E96; SizeX_mm: 1; SizeY_mm: 0.5; SizeZ_mm: 0.6; Value2: 0.063W; AEC Qualified: Y; VDC_V: 50V; AEC Category: Q200; AEC Grade: 0
R291 R292 R305 = CMP-0026658-1: as R287 on sheet PROC111_AM263x_7_PRU
R293 R294 = CMP-0078193-1: as R96 on sheet PROC111_AM263x_7_PRU
TP7 = CMP-0078143-3: TEST POINT.  No entry in BOM.
U22 = CMP-0091377-1: 1/1 Transceiver Ethernet 48-VQFN (7x7); Manufacturer: Texas Instruments; TaMin_C: -40°C; SizeZ_mm: 1mm; TaMax_C: +125°C; Max Supply Voltage: 3.45V; Number Of Channels: 1; AEC Qualified: No; Data Rate: 1000Mbits/s; Min Supply Voltage: 990mV; Simplex Duplex: Full-Duplex; Standoff Height: 0mm
U50 = CMP-0093539-2: as U23 on sheet PROC111_AM263x_7_PRU
Y2 = CMP-0084811-1: Crystal, 25 MHz, 10 ppm, 4 pF, SMD; Manufacturer: Abracon Corporation; Load Capacitance: 4 pF; TaMax_C: 85°C; SizeY_mm: 2.5; SizeAreaWB_mm2: 10.5; AEC Category: Q200; Frequency Stability: 20 ppm; SizeX_mm: 2; SizeArea_mm2: 5; SizeZ_mm: 0.6; AEC Qualified: N; TaMin_C: -40°C; Frequency Tolerance: 10 ppm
